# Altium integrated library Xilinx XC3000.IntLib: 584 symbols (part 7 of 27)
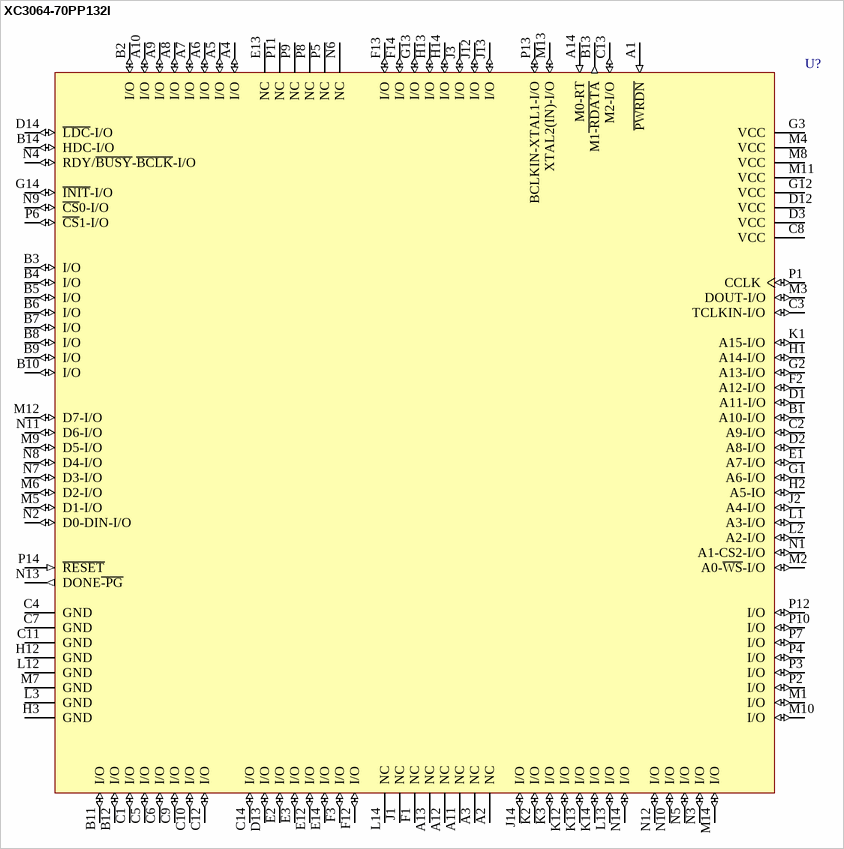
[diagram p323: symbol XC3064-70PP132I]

## XC3064-70PP132I
designator U?
Logic Cell Array with 224 CLBs, with 96 I/O Pins, 132-Pin PGA, Industrial Grade; ComponentAvailability: Not for New Design
footprint PP132 (PGA, 132-Leads, Body 37x37mm, Pitch 2.54mm)
3D model XC3064-PP132 (132-Pin Plastic Pin Grid Array (PP132))
pins: A1 ~{PWRDN} (in), A2 NC, A3 NC, A4 I/O (io), A5 I/O (io), A6 I/O (io), A7 I/O (io), A8 I/O (io), A9 I/O (io), A10 I/O (io), A11 NC, A12 NC, A13 NC, A14 M0-RT (in), B1 A10-I/O (io), B2 I/O (io), B3 I/O (io), B4 I/O (io), B5 I/O (io), B6 I/O (io), B7 I/O (io), B8 I/O (io), B9 I/O (io), B10 I/O (io), B11 I/O (io), B12 I/O (io), B13 M1~{-RDATA} (out), B14 HDC-I/O (io), C1 I/O (io), C2 A9-I/O (io), C3 TCLKIN-I/O (io), C4 GND (power), C5 I/O (io), C6 I/O (io), C7 GND (power), C8 VCC (power), C9 I/O (io), C10 I/O (io), C11 GND (power), C12 I/O (io), C13 M2-I/O (io), C14 I/O (io), D1 A11-I/O (io), D2 A8-I/O (io), D3 VCC (power), D12 VCC (power), D13 I/O (io), D14 ~{LDC}-I/O (io), E1 A7-I/O (io), E2 I/O (io), E3 I/O (io), E12 I/O (io), E13 NC, E14 I/O (io), F1 NC, F2 A12-I/O (io), F3 I/O (io), F12 I/O (io), F13 I/O (io), F14 I/O (io), G1 A6-I/O (io), G2 A13-I/O (io), G3 VCC (power), G12 VCC (power), G13 I/O (io), G14 ~{INIT}-I/O (io), H1 A14-I/O (io), H2 A5-IO (io), H3 GND (power), H12 GND (power), H13 I/O (io), H14 I/O (io), J1 NC, J2 A4-I/O (io), J3 I/O (io), J12 I/O (io), J13 I/O (io), J14 I/O (io), K1 A15-I/O (io), K2 I/O (io), K3 I/O (io), K12 I/O (io), K13 I/O (io), K14 I/O (io), L1 A3-I/O (io), L2 A2-I/O (io), L3 GND (power), L12 GND (power), L13 I/O (io), L14 NC, M1 I/O (io), M2 A0-~{WS}-I/O (io), M3 DOUT-I/O (io), M4 VCC (power), M5 D1-I/O (io), M6 D2-I/O (io), M7 GND (power), M8 VCC (power), M9 D5-I/O (io), M10 I/O (io), M11 VCC (power), M12 D7-I/O (io), M13 XTAL2(IN)-I/O (io), M14 I/O (io), N1 A1-CS2-I/O (io), N2 D0-DIN-I/O (io), N3 I/O (io), N4 RDY/~{BUSY}-~{BCLK}-I/O (io), N5 I/O (io), N6 NC, N7 D3-I/O (io), N8 D4-I/O (io), N9 ~{CS}0-I/O (io), N10 I/O (io), N11 D6-I/O (io), N12 I/O (io), N13 DONE~{-PG} (out), N14 I/O (io), P1 CCLK (io), P2 I/O (io), P3 I/O (io), P4 I/O (io), P5 NC, P6 ~{CS}1-I/O (io), P7 I/O (io), P8 NC, P9 NC, P10 I/O (io), P11 NC, P12 I/O (io), P13 BCLKIN-XTAL1-I/O (io), P14 ~{RESET} (in)

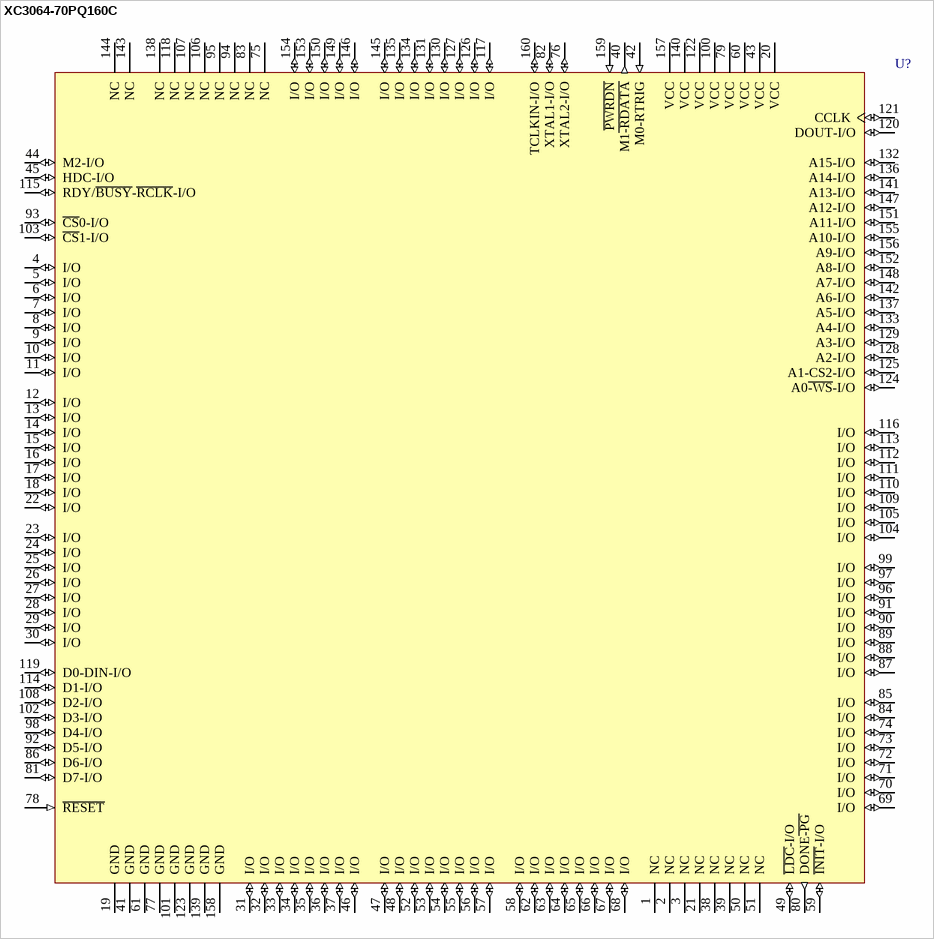
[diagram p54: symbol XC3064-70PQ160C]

## XC3064-70PQ160C
designator U?
Logic Cell Array with 224 CLBs, with 120 I/O Pins, 160-Pin PQFP, Commercial Grade; ComponentAvailability: Not for New Design
footprint PQ160_N (QFP, 160-Leads, Body 28 x 28mm, Pitch 0.65mm, IPC Medium Density)
footprint PQ160_L (QFP, 160-Leads, Body 28 x 28mm, Pitch 0.65mm, IPC High Density)
footprint PQ160_M (QFP, 160-Leads, Body 28 x 28mm, Pitch 0.65mm, IPC Low Density)
3D model XC3064-PQ160 (160-Pin Plastic Quad Flat Pack (PQ160))
pins: 1 NC, 2 NC, 3 NC, 4 I/O (io), 5 I/O (io), 6 I/O (io), 7 I/O (io), 8 I/O (io), 9 I/O (io), 10 I/O (io), 11 I/O (io), 12 I/O (io), 13 I/O (io), 14 I/O (io), 15 I/O (io), 16 I/O (io), 17 I/O (io), 18 I/O (io), 19 GND (power), 20 VCC (power), 21 NC, 22 I/O (io), 23 I/O (io), 24 I/O (io), 25 I/O (io), 26 I/O (io), 27 I/O (io), 28 I/O (io), 29 I/O (io), 30 I/O (io), 31 I/O (io), 32 I/O (io), 33 I/O (io), 34 I/O (io), 35 I/O (io), 36 I/O (io), 37 I/O (io), 38 NC, 39 NC, 40 M1~{-RDATA} (out), 41 GND (power), 42 M0-RTRIG (in), 43 VCC (power), 44 M2-I/O (io), 45 HDC-I/O (io), 46 I/O (io), 47 I/O (io), 48 I/O (io), 49 ~{LDC}-I/O (io), 50 NC, 51 NC, 52 I/O (io), 53 I/O (io), 54 I/O (io), 55 I/O (io), 56 I/O (io), 57 I/O (io), 58 I/O (io), 59 ~{INIT}-I/O (io), 60 VCC (power), 61 GND (power), 62 I/O (io), 63 I/O (io), 64 I/O (io), 65 I/O (io), 66 I/O (io), 67 I/O (io), 68 I/O (io), 69 I/O (io), 70 I/O (io), 71 I/O (io), 72 I/O (io), 73 I/O (io), 74 I/O (io), 75 NC, 76 XTAL2-I/O (io), 77 GND (power), 78 ~{RESET} (in), 79 VCC (power), 80 DONE~{-PG} (out), 81 D7-I/O (io), 82 XTAL1-I/O (io), 83 NC, 84 I/O (io), 85 I/O (io), 86 D6-I/O (io), 87 I/O (io), 88 I/O (io), 89 I/O (io), 90 I/O (io), 91 I/O (io), 92 D5-I/O (io), 93 ~{CS}0-I/O (io), 94 NC, 95 NC, 96 I/O (io), 97 I/O (io), 98 D4-I/O (io), 99 I/O (io), 100 VCC (power), 101 GND (power), 102 D3-I/O (io), 103 ~{CS}1-I/O (io), 104 I/O (io), 105 I/O (io), 106 NC, 107 NC, 108 D2-I/O (io), 109 I/O (io), 110 I/O (io), 111 I/O (io), 112 I/O (io), 113 I/O (io), 114 D1-I/O (io), 115 RDY/~{BUSY}-~{RCLK}-I/O (io), 116 I/O (io), 117 I/O (io), 118 NC, 119 D0-DIN-I/O (io), 120 DOUT-I/O (io), 121 CCLK (io), 122 VCC (power), 123 GND (power), 124 A0~{-WS}-I/O (io), 125 A1-CS2-I/O (io), 126 I/O (io), 127 I/O (io), 128 A2-I/O (io), 129 A3-I/O (io), 130 I/O (io), 131 I/O (io), 132 A15-I/O (io), 133 A4-I/O (io), 134 I/O (io), 135 I/O (io), 136 A14-I/O (io), 137 A5-I/O (io), 138 NC, 139 GND (power), 140 VCC (power), 141 A13-I/O (io), 142 A6-I/O (io), 143 NC, 144 NC, 145 I/O (io), 146 I/O (io), 147 A12-I/O (io), 148 A7-I/O (io), 149 I/O (io), 150 I/O (io), 151 A11-I/O (io), 152 A8-I/O (io), 153 I/O (io), 154 I/O (io), 155 A10-I/O (io), 156 A9-I/O (io), 157 VCC (power), 158 GND (power), 159 ~{PWRDN} (in), 160 TCLKIN-I/O (io)

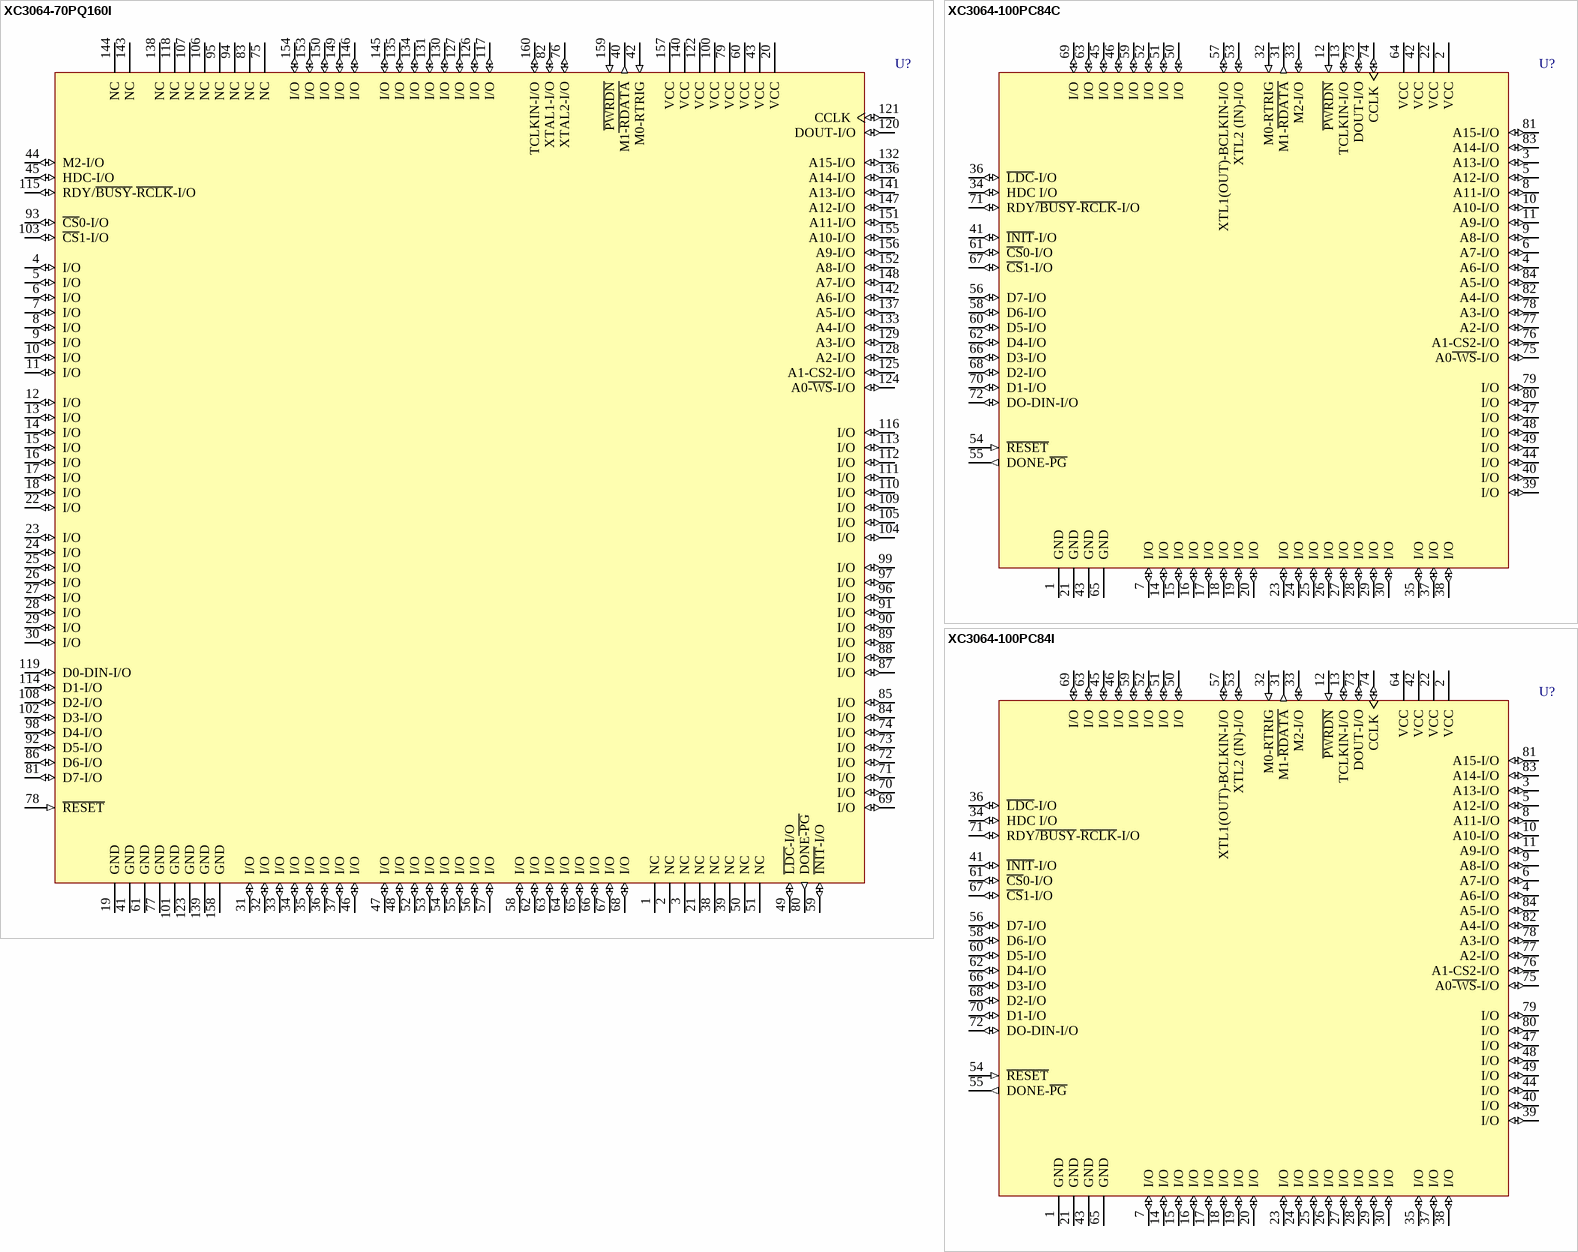
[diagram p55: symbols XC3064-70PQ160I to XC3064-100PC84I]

## XC3064-70PQ160I
designator U?
Logic Cell Array with 224 CLBs, with 120 I/O Pins, 160-Pin PQFP, Industrial Grade; ComponentAvailability: Not for New Design
footprint PQ160_N (QFP, 160-Leads, Body 28 x 28mm, Pitch 0.65mm, IPC Medium Density)
footprint PQ160_L (QFP, 160-Leads, Body 28 x 28mm, Pitch 0.65mm, IPC High Density)
footprint PQ160_M (QFP, 160-Leads, Body 28 x 28mm, Pitch 0.65mm, IPC Low Density)
3D model XC3064-PQ160 (160-Pin Plastic Quad Flat Pack (PQ160))
pins: 1 NC, 2 NC, 3 NC, 4 I/O (io), 5 I/O (io), 6 I/O (io), 7 I/O (io), 8 I/O (io), 9 I/O (io), 10 I/O (io), 11 I/O (io), 12 I/O (io), 13 I/O (io), 14 I/O (io), 15 I/O (io), 16 I/O (io), 17 I/O (io), 18 I/O (io), 19 GND (power), 20 VCC (power), 21 NC, 22 I/O (io), 23 I/O (io), 24 I/O (io), 25 I/O (io), 26 I/O (io), 27 I/O (io), 28 I/O (io), 29 I/O (io), 30 I/O (io), 31 I/O (io), 32 I/O (io), 33 I/O (io), 34 I/O (io), 35 I/O (io), 36 I/O (io), 37 I/O (io), 38 NC, 39 NC, 40 M1~{-RDATA} (out), 41 GND (power), 42 M0-RTRIG (in), 43 VCC (power), 44 M2-I/O (io), 45 HDC-I/O (io), 46 I/O (io), 47 I/O (io), 48 I/O (io), 49 ~{LDC}-I/O (io), 50 NC, 51 NC, 52 I/O (io), 53 I/O (io), 54 I/O (io), 55 I/O (io), 56 I/O (io), 57 I/O (io), 58 I/O (io), 59 ~{INIT}-I/O (io), 60 VCC (power), 61 GND (power), 62 I/O (io), 63 I/O (io), 64 I/O (io), 65 I/O (io), 66 I/O (io), 67 I/O (io), 68 I/O (io), 69 I/O (io), 70 I/O (io), 71 I/O (io), 72 I/O (io), 73 I/O (io), 74 I/O (io), 75 NC, 76 XTAL2-I/O (io), 77 GND (power), 78 ~{RESET} (in), 79 VCC (power), 80 DONE~{-PG} (out), 81 D7-I/O (io), 82 XTAL1-I/O (io), 83 NC, 84 I/O (io), 85 I/O (io), 86 D6-I/O (io), 87 I/O (io), 88 I/O (io), 89 I/O (io), 90 I/O (io), 91 I/O (io), 92 D5-I/O (io), 93 ~{CS}0-I/O (io), 94 NC, 95 NC, 96 I/O (io), 97 I/O (io), 98 D4-I/O (io), 99 I/O (io), 100 VCC (power), 101 GND (power), 102 D3-I/O (io), 103 ~{CS}1-I/O (io), 104 I/O (io), 105 I/O (io), 106 NC, 107 NC, 108 D2-I/O (io), 109 I/O (io), 110 I/O (io), 111 I/O (io), 112 I/O (io), 113 I/O (io), 114 D1-I/O (io), 115 RDY/~{BUSY}-~{RCLK}-I/O (io), 116 I/O (io), 117 I/O (io), 118 NC, 119 D0-DIN-I/O (io), 120 DOUT-I/O (io), 121 CCLK (io), 122 VCC (power), 123 GND (power), 124 A0~{-WS}-I/O (io), 125 A1-CS2-I/O (io), 126 I/O (io), 127 I/O (io), 128 A2-I/O (io), 129 A3-I/O (io), 130 I/O (io), 131 I/O (io), 132 A15-I/O (io), 133 A4-I/O (io), 134 I/O (io), 135 I/O (io), 136 A14-I/O (io), 137 A5-I/O (io), 138 NC, 139 GND (power), 140 VCC (power), 141 A13-I/O (io), 142 A6-I/O (io), 143 NC, 144 NC, 145 I/O (io), 146 I/O (io), 147 A12-I/O (io), 148 A7-I/O (io), 149 I/O (io), 150 I/O (io), 151 A11-I/O (io), 152 A8-I/O (io), 153 I/O (io), 154 I/O (io), 155 A10-I/O (io), 156 A9-I/O (io), 157 VCC (power), 158 GND (power), 159 ~{PWRDN} (in), 160 TCLKIN-I/O (io)

## XC3064-100PC84C
designator U?
Logic Cell Array with 224 CLBs, with 70 I/O Pins, 84-Pin PLCC, Commercial Grade; ComponentAvailability: Not for New Design
footprint PC84_N (Leaded Chip Carrier, 84-Leads, Body 29.3x29.3mm, Pitch 1.27mm, IPC Medium Density)
footprint PC84_L (Leaded Chip Carrier, 84-Leads, Body 29.3x29.3mm, Pitch 1.27mm, IPC High Density)
footprint PC84_M (Leaded Chip Carrier, 84-Leads, Body 29.3x29.3mm, Pitch 1.27mm, IPC Low Density)
3D model XC3064-PC84 (84-Pin Plastic Leaded Chip Carrier (PC84))
pins: 1 GND (power), 2 VCC (power), 3 A13-I/O (io), 4 A6-I/O (io), 5 A12-I/O (io), 6 A7-I/O (io), 7 I/O (io), 8 A11-I/O (io), 9 A8-I/O (io), 10 A10-I/O (io), 11 A9-I/O (io), 12 ~{PWRDN} (in), 13 TCLKIN-I/O (io), 14 I/O (io), 15 I/O (io), 16 I/O (io), 17 I/O (io), 18 I/O (io), 19 I/O (io), 20 I/O (io), 21 GND (power), 22 VCC (power), 23 I/O (io), 24 I/O (io), 25 I/O (io), 26 I/O (io), 27 I/O (io), 28 I/O (io), 29 I/O (io), 30 I/O (io), 31 M1-~{RDATA} (out), 32 M0-RTRIG (in), 33 M2-I/O (io), 34 HDC I/O (io), 35 I/O (io), 36 ~{LDC}-I/O (io), 37 I/O (io), 38 I/O (io), 39 I/O (io), 40 I/O (io), 41 ~{INIT}-I/O (io), 42 VCC (power), 43 GND (power), 44 I/O (io), 45 I/O (io), 46 I/O (io), 47 I/O (io), 48 I/O (io), 49 I/O (io), 50 I/O (io), 51 I/O (io), 52 I/O (io), 53 XTL2 (IN)-I/O (io), 54 ~{RESET} (in), 55 DONE-~{PG} (out), 56 D7-I/O (io), 57 XTL1(OUT)-BCLKIN-I/O (io), 58 D6-I/O (io), 59 I/O (io), 60 D5-I/O (io), 61 ~{CS}0-I/O (io), 62 D4-I/O (io), 63 I/O (io), 64 VCC (power), 65 GND (power), 66 D3-I/O (io), 67 ~{CS}1-I/O (io), 68 D2-I/O (io), 69 I/O (io), 70 D1-I/O (io), 71 RDY~{/BUSY}-~{RCLK}-I/O (io), 72 DO-DIN-I/O (io), 73 DOUT-I/O (io), 74 CCLK (io), 75 A0~{-WS}-I/O (io), 76 A1-CS2-I/O (io), 77 A2-I/O (io), 78 A3-I/O (io), 79 I/O (io), 80 I/O (io), 81 A15-I/O (io), 82 A4-I/O (io), 83 A14-I/O (io), 84 A5-I/O (io)

## XC3064-100PC84I
designator U?
Logic Cell Array with 224 CLBs, with 70 I/O Pins, 84-Pin PLCC, Industrial Grade; ComponentAvailability: Not for New Design
footprint PC84_N (Leaded Chip Carrier, 84-Leads, Body 29.3x29.3mm, Pitch 1.27mm, IPC Medium Density)
footprint PC84_L (Leaded Chip Carrier, 84-Leads, Body 29.3x29.3mm, Pitch 1.27mm, IPC High Density)
footprint PC84_M (Leaded Chip Carrier, 84-Leads, Body 29.3x29.3mm, Pitch 1.27mm, IPC Low Density)
3D model XC3064-PC84 (84-Pin Plastic Leaded Chip Carrier (PC84))
pins: 1 GND (power), 2 VCC (power), 3 A13-I/O (io), 4 A6-I/O (io), 5 A12-I/O (io), 6 A7-I/O (io), 7 I/O (io), 8 A11-I/O (io), 9 A8-I/O (io), 10 A10-I/O (io), 11 A9-I/O (io), 12 ~{PWRDN} (in), 13 TCLKIN-I/O (io), 14 I/O (io), 15 I/O (io), 16 I/O (io), 17 I/O (io), 18 I/O (io), 19 I/O (io), 20 I/O (io), 21 GND (power), 22 VCC (power), 23 I/O (io), 24 I/O (io), 25 I/O (io), 26 I/O (io), 27 I/O (io), 28 I/O (io), 29 I/O (io), 30 I/O (io), 31 M1-~{RDATA} (out), 32 M0-RTRIG (in), 33 M2-I/O (io), 34 HDC I/O (io), 35 I/O (io), 36 ~{LDC}-I/O (io), 37 I/O (io), 38 I/O (io), 39 I/O (io), 40 I/O (io), 41 ~{INIT}-I/O (io), 42 VCC (power), 43 GND (power), 44 I/O (io), 45 I/O (io), 46 I/O (io), 47 I/O (io), 48 I/O (io), 49 I/O (io), 50 I/O (io), 51 I/O (io), 52 I/O (io), 53 XTL2 (IN)-I/O (io), 54 ~{RESET} (in), 55 DONE-~{PG} (out), 56 D7-I/O (io), 57 XTL1(OUT)-BCLKIN-I/O (io), 58 D6-I/O (io), 59 I/O (io), 60 D5-I/O (io), 61 ~{CS}0-I/O (io), 62 D4-I/O (io), 63 I/O (io), 64 VCC (power), 65 GND (power), 66 D3-I/O (io), 67 ~{CS}1-I/O (io), 68 D2-I/O (io), 69 I/O (io), 70 D1-I/O (io), 71 RDY~{/BUSY}-~{RCLK}-I/O (io), 72 DO-DIN-I/O (io), 73 DOUT-I/O (io), 74 CCLK (io), 75 A0~{-WS}-I/O (io), 76 A1-CS2-I/O (io), 77 A2-I/O (io), 78 A3-I/O (io), 79 I/O (io), 80 I/O (io), 81 A15-I/O (io), 82 A4-I/O (io), 83 A14-I/O (io), 84 A5-I/O (io)

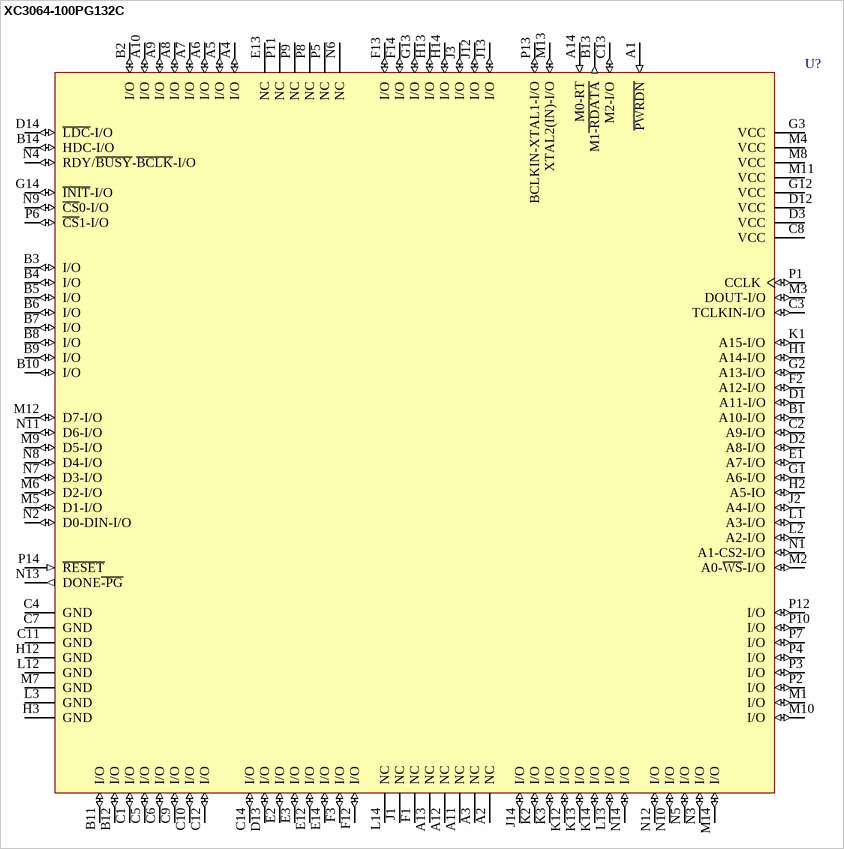
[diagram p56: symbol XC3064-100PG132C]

## XC3064-100PG132C
designator U?
Logic Cell Array with 224 CLBs, with 96 I/O Pins, 132-Pin PGA, Commercial Grade; ComponentAvailability: Not for New Design
footprint PG132 (PGA, 132-Leads, Body 37x37mm, Pitch 2.54mm)
3D model XC3064-PG132 (132-Pin Ceramic Pin Grid Array (PG132))
pins: A1 ~{PWRDN} (in), A2 NC, A3 NC, A4 I/O (io), A5 I/O (io), A6 I/O (io), A7 I/O (io), A8 I/O (io), A9 I/O (io), A10 I/O (io), A11 NC, A12 NC, A13 NC, A14 M0-RT (in), B1 A10-I/O (io), B2 I/O (io), B3 I/O (io), B4 I/O (io), B5 I/O (io), B6 I/O (io), B7 I/O (io), B8 I/O (io), B9 I/O (io), B10 I/O (io), B11 I/O (io), B12 I/O (io), B13 M1~{-RDATA} (out), B14 HDC-I/O (io), C1 I/O (io), C2 A9-I/O (io), C3 TCLKIN-I/O (io), C4 GND (power), C5 I/O (io), C6 I/O (io), C7 GND (power), C8 VCC (power), C9 I/O (io), C10 I/O (io), C11 GND (power), C12 I/O (io), C13 M2-I/O (io), C14 I/O (io), D1 A11-I/O (io), D2 A8-I/O (io), D3 VCC (power), D12 VCC (power), D13 I/O (io), D14 ~{LDC}-I/O (io), E1 A7-I/O (io), E2 I/O (io), E3 I/O (io), E12 I/O (io), E13 NC, E14 I/O (io), F1 NC, F2 A12-I/O (io), F3 I/O (io), F12 I/O (io), F13 I/O (io), F14 I/O (io), G1 A6-I/O (io), G2 A13-I/O (io), G3 VCC (power), G12 VCC (power), G13 I/O (io), G14 ~{INIT}-I/O (io), H1 A14-I/O (io), H2 A5-IO (io), H3 GND (power), H12 GND (power), H13 I/O (io), H14 I/O (io), J1 NC, J2 A4-I/O (io), J3 I/O (io), J12 I/O (io), J13 I/O (io), J14 I/O (io), K1 A15-I/O (io), K2 I/O (io), K3 I/O (io), K12 I/O (io), K13 I/O (io), K14 I/O (io), L1 A3-I/O (io), L2 A2-I/O (io), L3 GND (power), L12 GND (power), L13 I/O (io), L14 NC, M1 I/O (io), M2 A0-~{WS}-I/O (io), M3 DOUT-I/O (io), M4 VCC (power), M5 D1-I/O (io), M6 D2-I/O (io), M7 GND (power), M8 VCC (power), M9 D5-I/O (io), M10 I/O (io), M11 VCC (power), M12 D7-I/O (io), M13 XTAL2(IN)-I/O (io), M14 I/O (io), N1 A1-CS2-I/O (io), N2 D0-DIN-I/O (io), N3 I/O (io), N4 RDY/~{BUSY}-~{BCLK}-I/O (io), N5 I/O (io), N6 NC, N7 D3-I/O (io), N8 D4-I/O (io), N9 ~{CS}0-I/O (io), N10 I/O (io), N11 D6-I/O (io), N12 I/O (io), N13 DONE~{-PG} (out), N14 I/O (io), P1 CCLK (io), P2 I/O (io), P3 I/O (io), P4 I/O (io), P5 NC, P6 ~{CS}1-I/O (io), P7 I/O (io), P8 NC, P9 NC, P10 I/O (io), P11 NC, P12 I/O (io), P13 BCLKIN-XTAL1-I/O (io), P14 ~{RESET} (in)

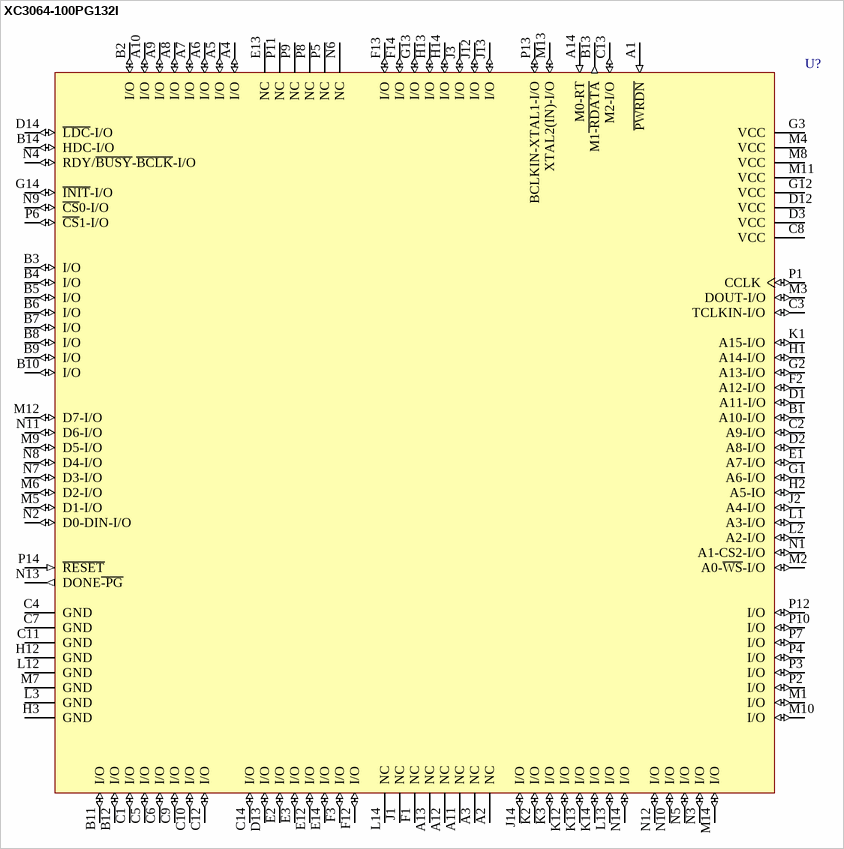
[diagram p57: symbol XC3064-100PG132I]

## XC3064-100PG132I
designator U?
Logic Cell Array with 224 CLBs, with 96 I/O Pins, 132-Pin PGA, Industrial Grade; ComponentAvailability: Not for New Design
footprint PG132 (PGA, 132-Leads, Body 37x37mm, Pitch 2.54mm)
3D model XC3064-PG132 (132-Pin Ceramic Pin Grid Array (PG132))
pins: A1 ~{PWRDN} (in), A2 NC, A3 NC, A4 I/O (io), A5 I/O (io), A6 I/O (io), A7 I/O (io), A8 I/O (io), A9 I/O (io), A10 I/O (io), A11 NC, A12 NC, A13 NC, A14 M0-RT (in), B1 A10-I/O (io), B2 I/O (io), B3 I/O (io), B4 I/O (io), B5 I/O (io), B6 I/O (io), B7 I/O (io), B8 I/O (io), B9 I/O (io), B10 I/O (io), B11 I/O (io), B12 I/O (io), B13 M1~{-RDATA} (out), B14 HDC-I/O (io), C1 I/O (io), C2 A9-I/O (io), C3 TCLKIN-I/O (io), C4 GND (power), C5 I/O (io), C6 I/O (io), C7 GND (power), C8 VCC (power), C9 I/O (io), C10 I/O (io), C11 GND (power), C12 I/O (io), C13 M2-I/O (io), C14 I/O (io), D1 A11-I/O (io), D2 A8-I/O (io), D3 VCC (power), D12 VCC (power), D13 I/O (io), D14 ~{LDC}-I/O (io), E1 A7-I/O (io), E2 I/O (io), E3 I/O (io), E12 I/O (io), E13 NC, E14 I/O (io), F1 NC, F2 A12-I/O (io), F3 I/O (io), F12 I/O (io), F13 I/O (io), F14 I/O (io), G1 A6-I/O (io), G2 A13-I/O (io), G3 VCC (power), G12 VCC (power), G13 I/O (io), G14 ~{INIT}-I/O (io), H1 A14-I/O (io), H2 A5-IO (io), H3 GND (power), H12 GND (power), H13 I/O (io), H14 I/O (io), J1 NC, J2 A4-I/O (io), J3 I/O (io), J12 I/O (io), J13 I/O (io), J14 I/O (io), K1 A15-I/O (io), K2 I/O (io), K3 I/O (io), K12 I/O (io), K13 I/O (io), K14 I/O (io), L1 A3-I/O (io), L2 A2-I/O (io), L3 GND (power), L12 GND (power), L13 I/O (io), L14 NC, M1 I/O (io), M2 A0-~{WS}-I/O (io), M3 DOUT-I/O (io), M4 VCC (power), M5 D1-I/O (io), M6 D2-I/O (io), M7 GND (power), M8 VCC (power), M9 D5-I/O (io), M10 I/O (io), M11 VCC (power), M12 D7-I/O (io), M13 XTAL2(IN)-I/O (io), M14 I/O (io), N1 A1-CS2-I/O (io), N2 D0-DIN-I/O (io), N3 I/O (io), N4 RDY/~{BUSY}-~{BCLK}-I/O (io), N5 I/O (io), N6 NC, N7 D3-I/O (io), N8 D4-I/O (io), N9 ~{CS}0-I/O (io), N10 I/O (io), N11 D6-I/O (io), N12 I/O (io), N13 DONE~{-PG} (out), N14 I/O (io), P1 CCLK (io), P2 I/O (io), P3 I/O (io), P4 I/O (io), P5 NC, P6 ~{CS}1-I/O (io), P7 I/O (io), P8 NC, P9 NC, P10 I/O (io), P11 NC, P12 I/O (io), P13 BCLKIN-XTAL1-I/O (io), P14 ~{RESET} (in)

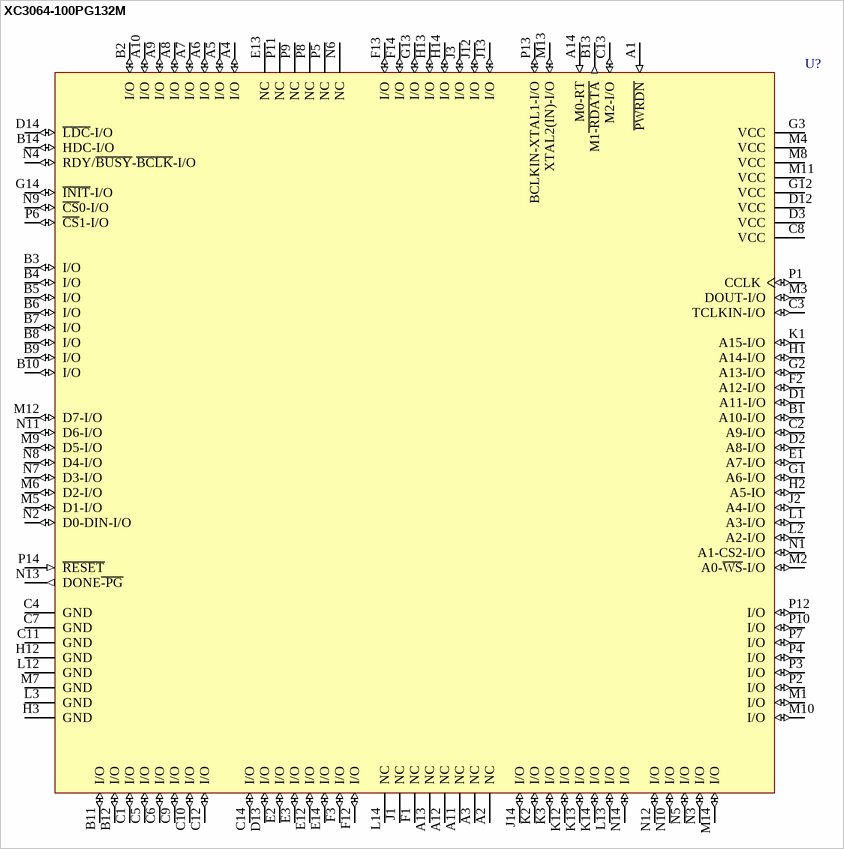
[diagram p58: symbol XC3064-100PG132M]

## XC3064-100PG132M
designator U?
Logic Cell Array with 224 CLBs, with 96 I/O Pins, 132-Pin PGA, Military Grade; ComponentAvailability: Not for New Design
footprint PG132 (PGA, 132-Leads, Body 37x37mm, Pitch 2.54mm)
3D model XC3064-PG132 (132-Pin Ceramic Pin Grid Array (PG132))
pins: A1 ~{PWRDN} (in), A2 NC, A3 NC, A4 I/O (io), A5 I/O (io), A6 I/O (io), A7 I/O (io), A8 I/O (io), A9 I/O (io), A10 I/O (io), A11 NC, A12 NC, A13 NC, A14 M0-RT (in), B1 A10-I/O (io), B2 I/O (io), B3 I/O (io), B4 I/O (io), B5 I/O (io), B6 I/O (io), B7 I/O (io), B8 I/O (io), B9 I/O (io), B10 I/O (io), B11 I/O (io), B12 I/O (io), B13 M1~{-RDATA} (out), B14 HDC-I/O (io), C1 I/O (io), C2 A9-I/O (io), C3 TCLKIN-I/O (io), C4 GND (power), C5 I/O (io), C6 I/O (io), C7 GND (power), C8 VCC (power), C9 I/O (io), C10 I/O (io), C11 GND (power), C12 I/O (io), C13 M2-I/O (io), C14 I/O (io), D1 A11-I/O (io), D2 A8-I/O (io), D3 VCC (power), D12 VCC (power), D13 I/O (io), D14 ~{LDC}-I/O (io), E1 A7-I/O (io), E2 I/O (io), E3 I/O (io), E12 I/O (io), E13 NC, E14 I/O (io), F1 NC, F2 A12-I/O (io), F3 I/O (io), F12 I/O (io), F13 I/O (io), F14 I/O (io), G1 A6-I/O (io), G2 A13-I/O (io), G3 VCC (power), G12 VCC (power), G13 I/O (io), G14 ~{INIT}-I/O (io), H1 A14-I/O (io), H2 A5-IO (io), H3 GND (power), H12 GND (power), H13 I/O (io), H14 I/O (io), J1 NC, J2 A4-I/O (io), J3 I/O (io), J12 I/O (io), J13 I/O (io), J14 I/O (io), K1 A15-I/O (io), K2 I/O (io), K3 I/O (io), K12 I/O (io), K13 I/O (io), K14 I/O (io), L1 A3-I/O (io), L2 A2-I/O (io), L3 GND (power), L12 GND (power), L13 I/O (io), L14 NC, M1 I/O (io), M2 A0-~{WS}-I/O (io), M3 DOUT-I/O (io), M4 VCC (power), M5 D1-I/O (io), M6 D2-I/O (io), M7 GND (power), M8 VCC (power), M9 D5-I/O (io), M10 I/O (io), M11 VCC (power), M12 D7-I/O (io), M13 XTAL2(IN)-I/O (io), M14 I/O (io), N1 A1-CS2-I/O (io), N2 D0-DIN-I/O (io), N3 I/O (io), N4 RDY/~{BUSY}-~{BCLK}-I/O (io), N5 I/O (io), N6 NC, N7 D3-I/O (io), N8 D4-I/O (io), N9 ~{CS}0-I/O (io), N10 I/O (io), N11 D6-I/O (io), N12 I/O (io), N13 DONE~{-PG} (out), N14 I/O (io), P1 CCLK (io), P2 I/O (io), P3 I/O (io), P4 I/O (io), P5 NC, P6 ~{CS}1-I/O (io), P7 I/O (io), P8 NC, P9 NC, P10 I/O (io), P11 NC, P12 I/O (io), P13 BCLKIN-XTAL1-I/O (io), P14 ~{RESET} (in)

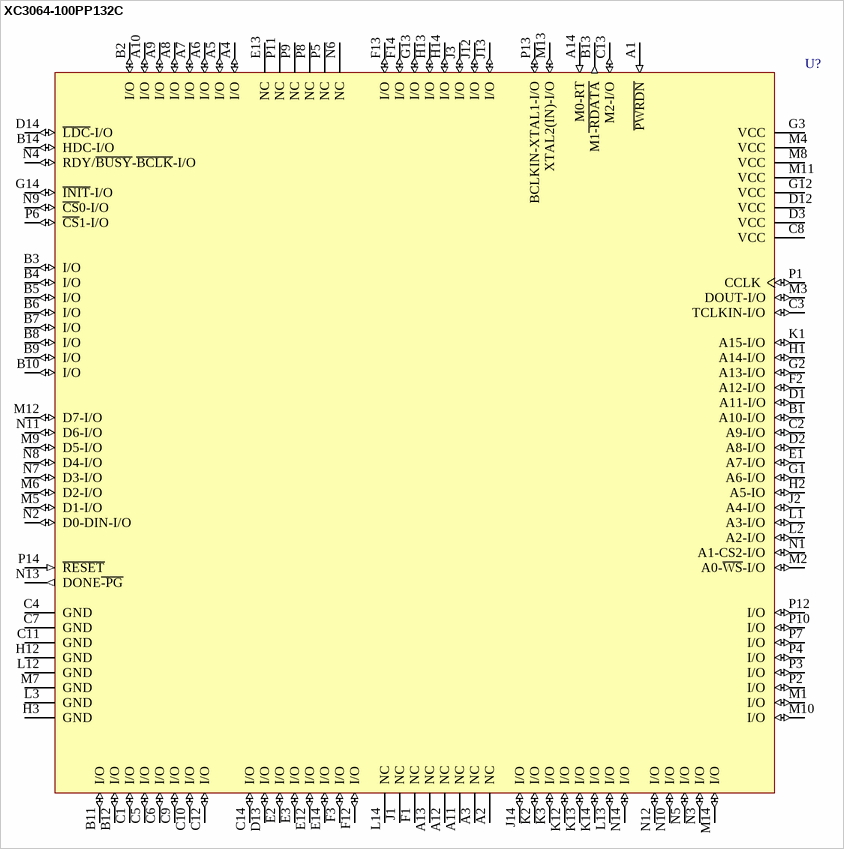
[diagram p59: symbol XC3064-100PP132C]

## XC3064-100PP132C
designator U?
Logic Cell Array with 224 CLBs, with 96 I/O Pins, 132-Pin PGA, Commercial Grade; ComponentAvailability: Not for New Design
footprint PP132 (PGA, 132-Leads, Body 37x37mm, Pitch 2.54mm)
3D model XC3064-PP132 (132-Pin Plastic Pin Grid Array (PP132))
pins: A1 ~{PWRDN} (in), A2 NC, A3 NC, A4 I/O (io), A5 I/O (io), A6 I/O (io), A7 I/O (io), A8 I/O (io), A9 I/O (io), A10 I/O (io), A11 NC, A12 NC, A13 NC, A14 M0-RT (in), B1 A10-I/O (io), B2 I/O (io), B3 I/O (io), B4 I/O (io), B5 I/O (io), B6 I/O (io), B7 I/O (io), B8 I/O (io), B9 I/O (io), B10 I/O (io), B11 I/O (io), B12 I/O (io), B13 M1~{-RDATA} (out), B14 HDC-I/O (io), C1 I/O (io), C2 A9-I/O (io), C3 TCLKIN-I/O (io), C4 GND (power), C5 I/O (io), C6 I/O (io), C7 GND (power), C8 VCC (power), C9 I/O (io), C10 I/O (io), C11 GND (power), C12 I/O (io), C13 M2-I/O (io), C14 I/O (io), D1 A11-I/O (io), D2 A8-I/O (io), D3 VCC (power), D12 VCC (power), D13 I/O (io), D14 ~{LDC}-I/O (io), E1 A7-I/O (io), E2 I/O (io), E3 I/O (io), E12 I/O (io), E13 NC, E14 I/O (io), F1 NC, F2 A12-I/O (io), F3 I/O (io), F12 I/O (io), F13 I/O (io), F14 I/O (io), G1 A6-I/O (io), G2 A13-I/O (io), G3 VCC (power), G12 VCC (power), G13 I/O (io), G14 ~{INIT}-I/O (io), H1 A14-I/O (io), H2 A5-IO (io), H3 GND (power), H12 GND (power), H13 I/O (io), H14 I/O (io), J1 NC, J2 A4-I/O (io), J3 I/O (io), J12 I/O (io), J13 I/O (io), J14 I/O (io), K1 A15-I/O (io), K2 I/O (io), K3 I/O (io), K12 I/O (io), K13 I/O (io), K14 I/O (io), L1 A3-I/O (io), L2 A2-I/O (io), L3 GND (power), L12 GND (power), L13 I/O (io), L14 NC, M1 I/O (io), M2 A0-~{WS}-I/O (io), M3 DOUT-I/O (io), M4 VCC (power), M5 D1-I/O (io), M6 D2-I/O (io), M7 GND (power), M8 VCC (power), M9 D5-I/O (io), M10 I/O (io), M11 VCC (power), M12 D7-I/O (io), M13 XTAL2(IN)-I/O (io), M14 I/O (io), N1 A1-CS2-I/O (io), N2 D0-DIN-I/O (io), N3 I/O (io), N4 RDY/~{BUSY}-~{BCLK}-I/O (io), N5 I/O (io), N6 NC, N7 D3-I/O (io), N8 D4-I/O (io), N9 ~{CS}0-I/O (io), N10 I/O (io), N11 D6-I/O (io), N12 I/O (io), N13 DONE~{-PG} (out), N14 I/O (io), P1 CCLK (io), P2 I/O (io), P3 I/O (io), P4 I/O (io), P5 NC, P6 ~{CS}1-I/O (io), P7 I/O (io), P8 NC, P9 NC, P10 I/O (io), P11 NC, P12 I/O (io), P13 BCLKIN-XTAL1-I/O (io), P14 ~{RESET} (in)

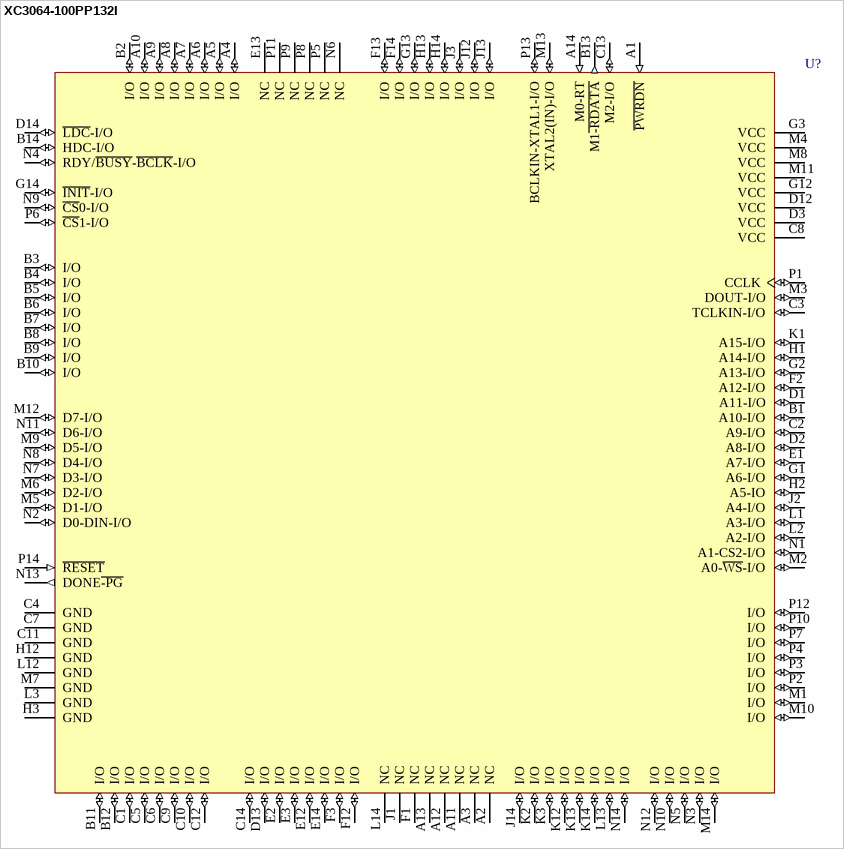
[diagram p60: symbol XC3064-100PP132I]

## XC3064-100PP132I
designator U?
Logic Cell Array with 224 CLBs, with 96 I/O Pins, 132-Pin PGA, Industrial Grade; ComponentAvailability: Not for New Design
footprint PP132 (PGA, 132-Leads, Body 37x37mm, Pitch 2.54mm)
3D model XC3064-PP132 (132-Pin Plastic Pin Grid Array (PP132))
pins: A1 ~{PWRDN} (in), A2 NC, A3 NC, A4 I/O (io), A5 I/O (io), A6 I/O (io), A7 I/O (io), A8 I/O (io), A9 I/O (io), A10 I/O (io), A11 NC, A12 NC, A13 NC, A14 M0-RT (in), B1 A10-I/O (io), B2 I/O (io), B3 I/O (io), B4 I/O (io), B5 I/O (io), B6 I/O (io), B7 I/O (io), B8 I/O (io), B9 I/O (io), B10 I/O (io), B11 I/O (io), B12 I/O (io), B13 M1~{-RDATA} (out), B14 HDC-I/O (io), C1 I/O (io), C2 A9-I/O (io), C3 TCLKIN-I/O (io), C4 GND (power), C5 I/O (io), C6 I/O (io), C7 GND (power), C8 VCC (power), C9 I/O (io), C10 I/O (io), C11 GND (power), C12 I/O (io), C13 M2-I/O (io), C14 I/O (io), D1 A11-I/O (io), D2 A8-I/O (io), D3 VCC (power), D12 VCC (power), D13 I/O (io), D14 ~{LDC}-I/O (io), E1 A7-I/O (io), E2 I/O (io), E3 I/O (io), E12 I/O (io), E13 NC, E14 I/O (io), F1 NC, F2 A12-I/O (io), F3 I/O (io), F12 I/O (io), F13 I/O (io), F14 I/O (io), G1 A6-I/O (io), G2 A13-I/O (io), G3 VCC (power), G12 VCC (power), G13 I/O (io), G14 ~{INIT}-I/O (io), H1 A14-I/O (io), H2 A5-IO (io), H3 GND (power), H12 GND (power), H13 I/O (io), H14 I/O (io), J1 NC, J2 A4-I/O (io), J3 I/O (io), J12 I/O (io), J13 I/O (io), J14 I/O (io), K1 A15-I/O (io), K2 I/O (io), K3 I/O (io), K12 I/O (io), K13 I/O (io), K14 I/O (io), L1 A3-I/O (io), L2 A2-I/O (io), L3 GND (power), L12 GND (power), L13 I/O (io), L14 NC, M1 I/O (io), M2 A0-~{WS}-I/O (io), M3 DOUT-I/O (io), M4 VCC (power), M5 D1-I/O (io), M6 D2-I/O (io), M7 GND (power), M8 VCC (power), M9 D5-I/O (io), M10 I/O (io), M11 VCC (power), M12 D7-I/O (io), M13 XTAL2(IN)-I/O (io), M14 I/O (io), N1 A1-CS2-I/O (io), N2 D0-DIN-I/O (io), N3 I/O (io), N4 RDY/~{BUSY}-~{BCLK}-I/O (io), N5 I/O (io), N6 NC, N7 D3-I/O (io), N8 D4-I/O (io), N9 ~{CS}0-I/O (io), N10 I/O (io), N11 D6-I/O (io), N12 I/O (io), N13 DONE~{-PG} (out), N14 I/O (io), P1 CCLK (io), P2 I/O (io), P3 I/O (io), P4 I/O (io), P5 NC, P6 ~{CS}1-I/O (io), P7 I/O (io), P8 NC, P9 NC, P10 I/O (io), P11 NC, P12 I/O (io), P13 BCLKIN-XTAL1-I/O (io), P14 ~{RESET} (in)

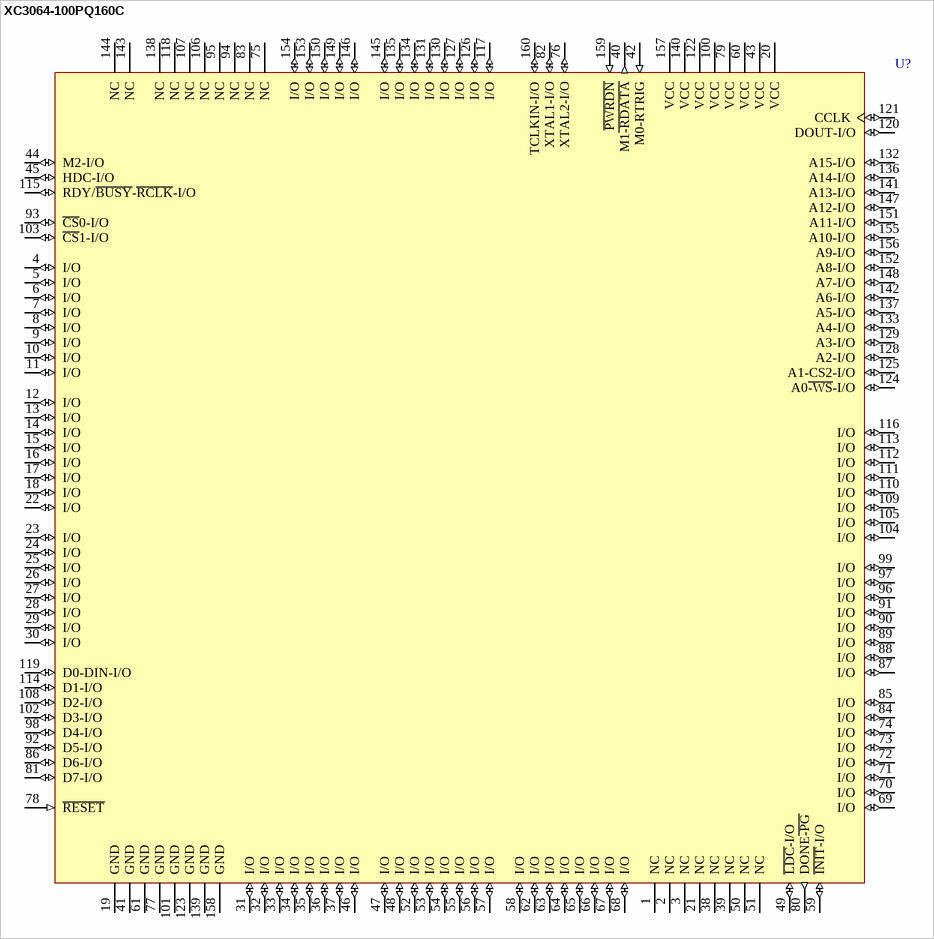
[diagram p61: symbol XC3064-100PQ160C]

## XC3064-100PQ160C
designator U?
Logic Cell Array with 224 CLBs, with 120 I/O Pins, 160-Pin PQFP, Commercial Grade; ComponentAvailability: Not for New Design
footprint PQ160_N (QFP, 160-Leads, Body 28 x 28mm, Pitch 0.65mm, IPC Medium Density)
footprint PQ160_L (QFP, 160-Leads, Body 28 x 28mm, Pitch 0.65mm, IPC High Density)
footprint PQ160_M (QFP, 160-Leads, Body 28 x 28mm, Pitch 0.65mm, IPC Low Density)
3D model XC3064-PQ160 (160-Pin Plastic Quad Flat Pack (PQ160))
pins: 1 NC, 2 NC, 3 NC, 4 I/O (io), 5 I/O (io), 6 I/O (io), 7 I/O (io), 8 I/O (io), 9 I/O (io), 10 I/O (io), 11 I/O (io), 12 I/O (io), 13 I/O (io), 14 I/O (io), 15 I/O (io), 16 I/O (io), 17 I/O (io), 18 I/O (io), 19 GND (power), 20 VCC (power), 21 NC, 22 I/O (io), 23 I/O (io), 24 I/O (io), 25 I/O (io), 26 I/O (io), 27 I/O (io), 28 I/O (io), 29 I/O (io), 30 I/O (io), 31 I/O (io), 32 I/O (io), 33 I/O (io), 34 I/O (io), 35 I/O (io), 36 I/O (io), 37 I/O (io), 38 NC, 39 NC, 40 M1~{-RDATA} (out), 41 GND (power), 42 M0-RTRIG (in), 43 VCC (power), 44 M2-I/O (io), 45 HDC-I/O (io), 46 I/O (io), 47 I/O (io), 48 I/O (io), 49 ~{LDC}-I/O (io), 50 NC, 51 NC, 52 I/O (io), 53 I/O (io), 54 I/O (io), 55 I/O (io), 56 I/O (io), 57 I/O (io), 58 I/O (io), 59 ~{INIT}-I/O (io), 60 VCC (power), 61 GND (power), 62 I/O (io), 63 I/O (io), 64 I/O (io), 65 I/O (io), 66 I/O (io), 67 I/O (io), 68 I/O (io), 69 I/O (io), 70 I/O (io), 71 I/O (io), 72 I/O (io), 73 I/O (io), 74 I/O (io), 75 NC, 76 XTAL2-I/O (io), 77 GND (power), 78 ~{RESET} (in), 79 VCC (power), 80 DONE~{-PG} (out), 81 D7-I/O (io), 82 XTAL1-I/O (io), 83 NC, 84 I/O (io), 85 I/O (io), 86 D6-I/O (io), 87 I/O (io), 88 I/O (io), 89 I/O (io), 90 I/O (io), 91 I/O (io), 92 D5-I/O (io), 93 ~{CS}0-I/O (io), 94 NC, 95 NC, 96 I/O (io), 97 I/O (io), 98 D4-I/O (io), 99 I/O (io), 100 VCC (power), 101 GND (power), 102 D3-I/O (io), 103 ~{CS}1-I/O (io), 104 I/O (io), 105 I/O (io), 106 NC, 107 NC, 108 D2-I/O (io), 109 I/O (io), 110 I/O (io), 111 I/O (io), 112 I/O (io), 113 I/O (io), 114 D1-I/O (io), 115 RDY/~{BUSY}-~{RCLK}-I/O (io), 116 I/O (io), 117 I/O (io), 118 NC, 119 D0-DIN-I/O (io), 120 DOUT-I/O (io), 121 CCLK (io), 122 VCC (power), 123 GND (power), 124 A0~{-WS}-I/O (io), 125 A1-CS2-I/O (io), 126 I/O (io), 127 I/O (io), 128 A2-I/O (io), 129 A3-I/O (io), 130 I/O (io), 131 I/O (io), 132 A15-I/O (io), 133 A4-I/O (io), 134 I/O (io), 135 I/O (io), 136 A14-I/O (io), 137 A5-I/O (io), 138 NC, 139 GND (power), 140 VCC (power), 141 A13-I/O (io), 142 A6-I/O (io), 143 NC, 144 NC, 145 I/O (io), 146 I/O (io), 147 A12-I/O (io), 148 A7-I/O (io), 149 I/O (io), 150 I/O (io), 151 A11-I/O (io), 152 A8-I/O (io), 153 I/O (io), 154 I/O (io), 155 A10-I/O (io), 156 A9-I/O (io), 157 VCC (power), 158 GND (power), 159 ~{PWRDN} (in), 160 TCLKIN-I/O (io)

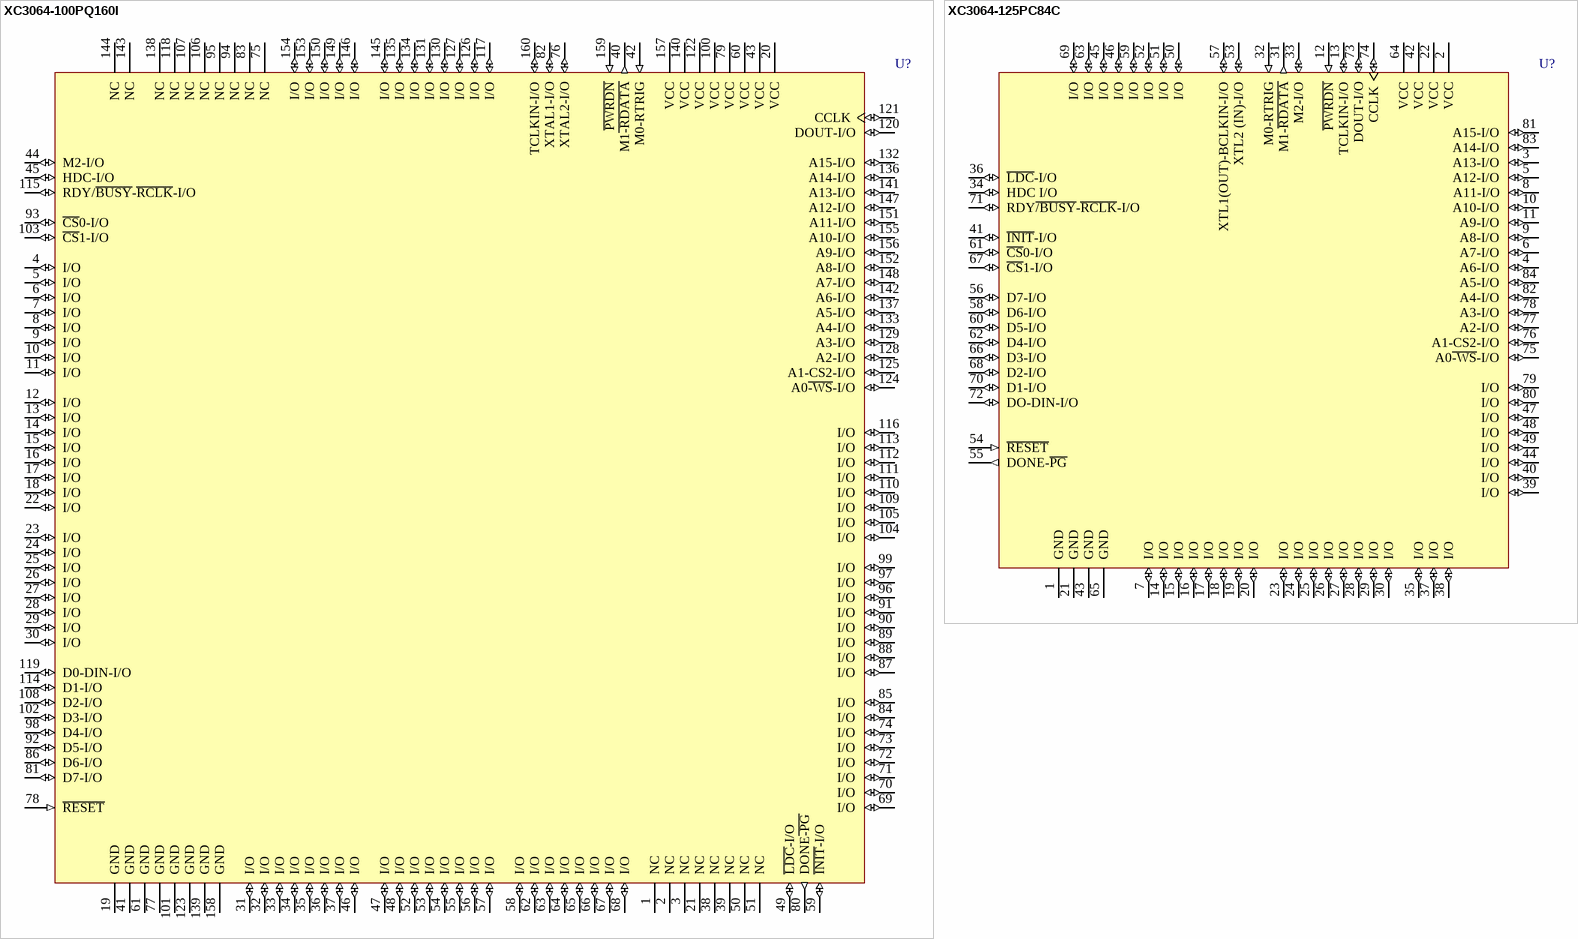
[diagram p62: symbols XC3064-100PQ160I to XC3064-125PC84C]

## XC3064-100PQ160I
designator U?
Logic Cell Array with 224 CLBs, with 120 I/O Pins, 160-Pin PQFP, Industrial Grade; ComponentAvailability: Not for New Design
footprint PQ160_N (QFP, 160-Leads, Body 28 x 28mm, Pitch 0.65mm, IPC Medium Density)
footprint PQ160_L (QFP, 160-Leads, Body 28 x 28mm, Pitch 0.65mm, IPC High Density)
footprint PQ160_M (QFP, 160-Leads, Body 28 x 28mm, Pitch 0.65mm, IPC Low Density)
3D model XC3064-PQ160 (160-Pin Plastic Quad Flat Pack (PQ160))
pins: 1 NC, 2 NC, 3 NC, 4 I/O (io), 5 I/O (io), 6 I/O (io), 7 I/O (io), 8 I/O (io), 9 I/O (io), 10 I/O (io), 11 I/O (io), 12 I/O (io), 13 I/O (io), 14 I/O (io), 15 I/O (io), 16 I/O (io), 17 I/O (io), 18 I/O (io), 19 GND (power), 20 VCC (power), 21 NC, 22 I/O (io), 23 I/O (io), 24 I/O (io), 25 I/O (io), 26 I/O (io), 27 I/O (io), 28 I/O (io), 29 I/O (io), 30 I/O (io), 31 I/O (io), 32 I/O (io), 33 I/O (io), 34 I/O (io), 35 I/O (io), 36 I/O (io), 37 I/O (io), 38 NC, 39 NC, 40 M1~{-RDATA} (out), 41 GND (power), 42 M0-RTRIG (in), 43 VCC (power), 44 M2-I/O (io), 45 HDC-I/O (io), 46 I/O (io), 47 I/O (io), 48 I/O (io), 49 ~{LDC}-I/O (io), 50 NC, 51 NC, 52 I/O (io), 53 I/O (io), 54 I/O (io), 55 I/O (io), 56 I/O (io), 57 I/O (io), 58 I/O (io), 59 ~{INIT}-I/O (io), 60 VCC (power), 61 GND (power), 62 I/O (io), 63 I/O (io), 64 I/O (io), 65 I/O (io), 66 I/O (io), 67 I/O (io), 68 I/O (io), 69 I/O (io), 70 I/O (io), 71 I/O (io), 72 I/O (io), 73 I/O (io), 74 I/O (io), 75 NC, 76 XTAL2-I/O (io), 77 GND (power), 78 ~{RESET} (in), 79 VCC (power), 80 DONE~{-PG} (out), 81 D7-I/O (io), 82 XTAL1-I/O (io), 83 NC, 84 I/O (io), 85 I/O (io), 86 D6-I/O (io), 87 I/O (io), 88 I/O (io), 89 I/O (io), 90 I/O (io), 91 I/O (io), 92 D5-I/O (io), 93 ~{CS}0-I/O (io), 94 NC, 95 NC, 96 I/O (io), 97 I/O (io), 98 D4-I/O (io), 99 I/O (io), 100 VCC (power), 101 GND (power), 102 D3-I/O (io), 103 ~{CS}1-I/O (io), 104 I/O (io), 105 I/O (io), 106 NC, 107 NC, 108 D2-I/O (io), 109 I/O (io), 110 I/O (io), 111 I/O (io), 112 I/O (io), 113 I/O (io), 114 D1-I/O (io), 115 RDY/~{BUSY}-~{RCLK}-I/O (io), 116 I/O (io), 117 I/O (io), 118 NC, 119 D0-DIN-I/O (io), 120 DOUT-I/O (io), 121 CCLK (io), 122 VCC (power), 123 GND (power), 124 A0~{-WS}-I/O (io), 125 A1-CS2-I/O (io), 126 I/O (io), 127 I/O (io), 128 A2-I/O (io), 129 A3-I/O (io), 130 I/O (io), 131 I/O (io), 132 A15-I/O (io), 133 A4-I/O (io), 134 I/O (io), 135 I/O (io), 136 A14-I/O (io), 137 A5-I/O (io), 138 NC, 139 GND (power), 140 VCC (power), 141 A13-I/O (io), 142 A6-I/O (io), 143 NC, 144 NC, 145 I/O (io), 146 I/O (io), 147 A12-I/O (io), 148 A7-I/O (io), 149 I/O (io), 150 I/O (io), 151 A11-I/O (io), 152 A8-I/O (io), 153 I/O (io), 154 I/O (io), 155 A10-I/O (io), 156 A9-I/O (io), 157 VCC (power), 158 GND (power), 159 ~{PWRDN} (in), 160 TCLKIN-I/O (io)

## XC3064-125PC84C
designator U?
Logic Cell Array with 224 CLBs, with 70 I/O Pins, 84-Pin PLCC, Commercial Grade; ComponentAvailability: Not for New Design
footprint PC84_N (Leaded Chip Carrier, 84-Leads, Body 29.3x29.3mm, Pitch 1.27mm, IPC Medium Density)
footprint PC84_L (Leaded Chip Carrier, 84-Leads, Body 29.3x29.3mm, Pitch 1.27mm, IPC High Density)
footprint PC84_M (Leaded Chip Carrier, 84-Leads, Body 29.3x29.3mm, Pitch 1.27mm, IPC Low Density)
3D model XC3064-PC84 (84-Pin Plastic Leaded Chip Carrier (PC84))
pins: 1 GND (power), 2 VCC (power), 3 A13-I/O (io), 4 A6-I/O (io), 5 A12-I/O (io), 6 A7-I/O (io), 7 I/O (io), 8 A11-I/O (io), 9 A8-I/O (io), 10 A10-I/O (io), 11 A9-I/O (io), 12 ~{PWRDN} (in), 13 TCLKIN-I/O (io), 14 I/O (io), 15 I/O (io), 16 I/O (io), 17 I/O (io), 18 I/O (io), 19 I/O (io), 20 I/O (io), 21 GND (power), 22 VCC (power), 23 I/O (io), 24 I/O (io), 25 I/O (io), 26 I/O (io), 27 I/O (io), 28 I/O (io), 29 I/O (io), 30 I/O (io), 31 M1-~{RDATA} (out), 32 M0-RTRIG (in), 33 M2-I/O (io), 34 HDC I/O (io), 35 I/O (io), 36 ~{LDC}-I/O (io), 37 I/O (io), 38 I/O (io), 39 I/O (io), 40 I/O (io), 41 ~{INIT}-I/O (io), 42 VCC (power), 43 GND (power), 44 I/O (io), 45 I/O (io), 46 I/O (io), 47 I/O (io), 48 I/O (io), 49 I/O (io), 50 I/O (io), 51 I/O (io), 52 I/O (io), 53 XTL2 (IN)-I/O (io), 54 ~{RESET} (in), 55 DONE-~{PG} (out), 56 D7-I/O (io), 57 XTL1(OUT)-BCLKIN-I/O (io), 58 D6-I/O (io), 59 I/O (io), 60 D5-I/O (io), 61 ~{CS}0-I/O (io), 62 D4-I/O (io), 63 I/O (io), 64 VCC (power), 65 GND (power), 66 D3-I/O (io), 67 ~{CS}1-I/O (io), 68 D2-I/O (io), 69 I/O (io), 70 D1-I/O (io), 71 RDY~{/BUSY}-~{RCLK}-I/O (io), 72 DO-DIN-I/O (io), 73 DOUT-I/O (io), 74 CCLK (io), 75 A0~{-WS}-I/O (io), 76 A1-CS2-I/O (io), 77 A2-I/O (io), 78 A3-I/O (io), 79 I/O (io), 80 I/O (io), 81 A15-I/O (io), 82 A4-I/O (io), 83 A14-I/O (io), 84 A5-I/O (io)

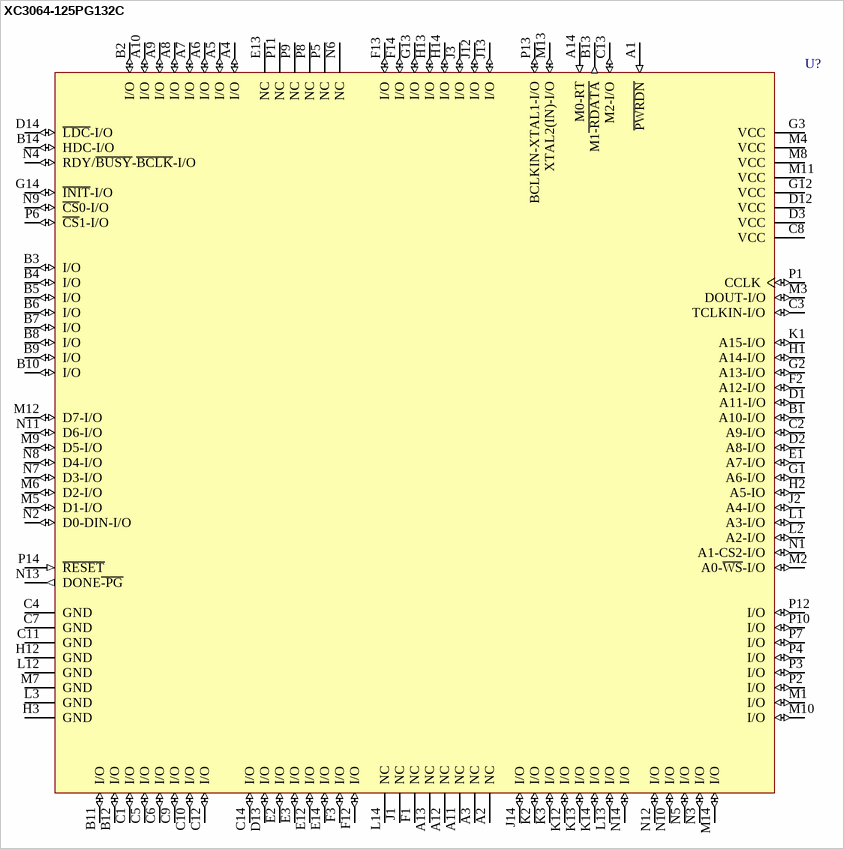
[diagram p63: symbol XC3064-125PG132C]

## XC3064-125PG132C
designator U?
Logic Cell Array with 224 CLBs, with 96 I/O Pins, 132-Pin PGA, Commercial Grade; ComponentAvailability: Not for New Design
footprint PG132 (PGA, 132-Leads, Body 37x37mm, Pitch 2.54mm)
3D model XC3064-PG132 (132-Pin Ceramic Pin Grid Array (PG132))
pins: A1 ~{PWRDN} (in), A2 NC, A3 NC, A4 I/O (io), A5 I/O (io), A6 I/O (io), A7 I/O (io), A8 I/O (io), A9 I/O (io), A10 I/O (io), A11 NC, A12 NC, A13 NC, A14 M0-RT (in), B1 A10-I/O (io), B2 I/O (io), B3 I/O (io), B4 I/O (io), B5 I/O (io), B6 I/O (io), B7 I/O (io), B8 I/O (io), B9 I/O (io), B10 I/O (io), B11 I/O (io), B12 I/O (io), B13 M1~{-RDATA} (out), B14 HDC-I/O (io), C1 I/O (io), C2 A9-I/O (io), C3 TCLKIN-I/O (io), C4 GND (power), C5 I/O (io), C6 I/O (io), C7 GND (power), C8 VCC (power), C9 I/O (io), C10 I/O (io), C11 GND (power), C12 I/O (io), C13 M2-I/O (io), C14 I/O (io), D1 A11-I/O (io), D2 A8-I/O (io), D3 VCC (power), D12 VCC (power), D13 I/O (io), D14 ~{LDC}-I/O (io), E1 A7-I/O (io), E2 I/O (io), E3 I/O (io), E12 I/O (io), E13 NC, E14 I/O (io), F1 NC, F2 A12-I/O (io), F3 I/O (io), F12 I/O (io), F13 I/O (io), F14 I/O (io), G1 A6-I/O (io), G2 A13-I/O (io), G3 VCC (power), G12 VCC (power), G13 I/O (io), G14 ~{INIT}-I/O (io), H1 A14-I/O (io), H2 A5-IO (io), H3 GND (power), H12 GND (power), H13 I/O (io), H14 I/O (io), J1 NC, J2 A4-I/O (io), J3 I/O (io), J12 I/O (io), J13 I/O (io), J14 I/O (io), K1 A15-I/O (io), K2 I/O (io), K3 I/O (io), K12 I/O (io), K13 I/O (io), K14 I/O (io), L1 A3-I/O (io), L2 A2-I/O (io), L3 GND (power), L12 GND (power), L13 I/O (io), L14 NC, M1 I/O (io), M2 A0-~{WS}-I/O (io), M3 DOUT-I/O (io), M4 VCC (power), M5 D1-I/O (io), M6 D2-I/O (io), M7 GND (power), M8 VCC (power), M9 D5-I/O (io), M10 I/O (io), M11 VCC (power), M12 D7-I/O (io), M13 XTAL2(IN)-I/O (io), M14 I/O (io), N1 A1-CS2-I/O (io), N2 D0-DIN-I/O (io), N3 I/O (io), N4 RDY/~{BUSY}-~{BCLK}-I/O (io), N5 I/O (io), N6 NC, N7 D3-I/O (io), N8 D4-I/O (io), N9 ~{CS}0-I/O (io), N10 I/O (io), N11 D6-I/O (io), N12 I/O (io), N13 DONE~{-PG} (out), N14 I/O (io), P1 CCLK (io), P2 I/O (io), P3 I/O (io), P4 I/O (io), P5 NC, P6 ~{CS}1-I/O (io), P7 I/O (io), P8 NC, P9 NC, P10 I/O (io), P11 NC, P12 I/O (io), P13 BCLKIN-XTAL1-I/O (io), P14 ~{RESET} (in)

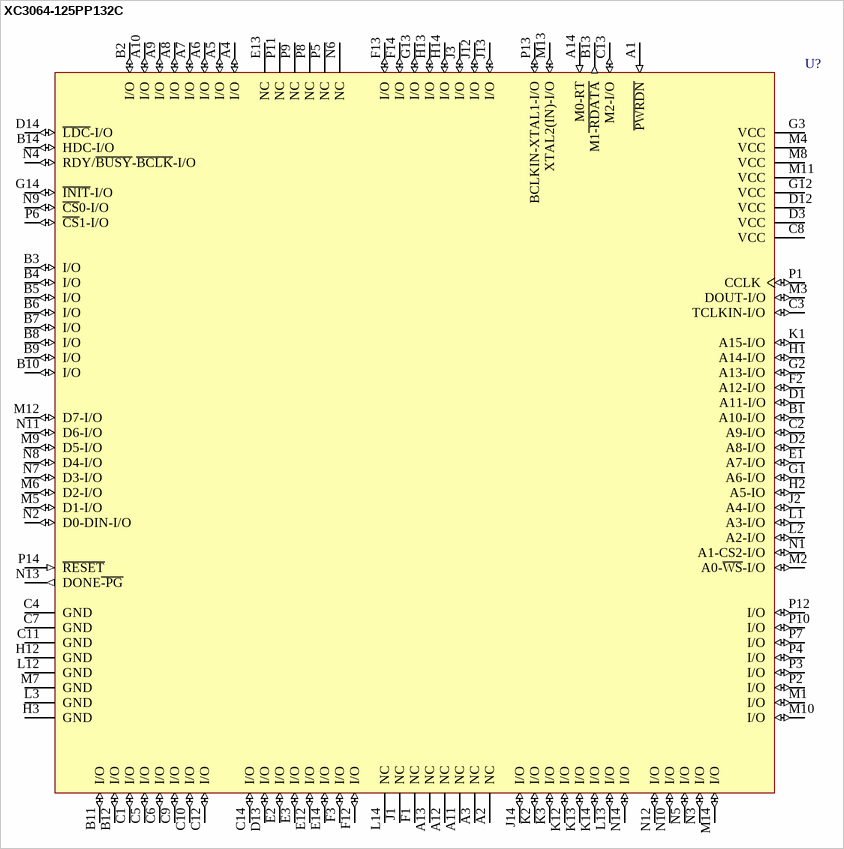
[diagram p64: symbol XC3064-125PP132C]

## XC3064-125PP132C
designator U?
Logic Cell Array with 224 CLBs, with 96 I/O Pins, 132-Pin PGA, Commercial Grade; ComponentAvailability: Not for New Design
footprint PP132 (PGA, 132-Leads, Body 37x37mm, Pitch 2.54mm)
3D model XC3064-PP132 (132-Pin Plastic Pin Grid Array (PP132))
pins: A1 ~{PWRDN} (in), A2 NC, A3 NC, A4 I/O (io), A5 I/O (io), A6 I/O (io), A7 I/O (io), A8 I/O (io), A9 I/O (io), A10 I/O (io), A11 NC, A12 NC, A13 NC, A14 M0-RT (in), B1 A10-I/O (io), B2 I/O (io), B3 I/O (io), B4 I/O (io), B5 I/O (io), B6 I/O (io), B7 I/O (io), B8 I/O (io), B9 I/O (io), B10 I/O (io), B11 I/O (io), B12 I/O (io), B13 M1~{-RDATA} (out), B14 HDC-I/O (io), C1 I/O (io), C2 A9-I/O (io), C3 TCLKIN-I/O (io), C4 GND (power), C5 I/O (io), C6 I/O (io), C7 GND (power), C8 VCC (power), C9 I/O (io), C10 I/O (io), C11 GND (power), C12 I/O (io), C13 M2-I/O (io), C14 I/O (io), D1 A11-I/O (io), D2 A8-I/O (io), D3 VCC (power), D12 VCC (power), D13 I/O (io), D14 ~{LDC}-I/O (io), E1 A7-I/O (io), E2 I/O (io), E3 I/O (io), E12 I/O (io), E13 NC, E14 I/O (io), F1 NC, F2 A12-I/O (io), F3 I/O (io), F12 I/O (io), F13 I/O (io), F14 I/O (io), G1 A6-I/O (io), G2 A13-I/O (io), G3 VCC (power), G12 VCC (power), G13 I/O (io), G14 ~{INIT}-I/O (io), H1 A14-I/O (io), H2 A5-IO (io), H3 GND (power), H12 GND (power), H13 I/O (io), H14 I/O (io), J1 NC, J2 A4-I/O (io), J3 I/O (io), J12 I/O (io), J13 I/O (io), J14 I/O (io), K1 A15-I/O (io), K2 I/O (io), K3 I/O (io), K12 I/O (io), K13 I/O (io), K14 I/O (io), L1 A3-I/O (io), L2 A2-I/O (io), L3 GND (power), L12 GND (power), L13 I/O (io), L14 NC, M1 I/O (io), M2 A0-~{WS}-I/O (io), M3 DOUT-I/O (io), M4 VCC (power), M5 D1-I/O (io), M6 D2-I/O (io), M7 GND (power), M8 VCC (power), M9 D5-I/O (io), M10 I/O (io), M11 VCC (power), M12 D7-I/O (io), M13 XTAL2(IN)-I/O (io), M14 I/O (io), N1 A1-CS2-I/O (io), N2 D0-DIN-I/O (io), N3 I/O (io), N4 RDY/~{BUSY}-~{BCLK}-I/O (io), N5 I/O (io), N6 NC, N7 D3-I/O (io), N8 D4-I/O (io), N9 ~{CS}0-I/O (io), N10 I/O (io), N11 D6-I/O (io), N12 I/O (io), N13 DONE~{-PG} (out), N14 I/O (io), P1 CCLK (io), P2 I/O (io), P3 I/O (io), P4 I/O (io), P5 NC, P6 ~{CS}1-I/O (io), P7 I/O (io), P8 NC, P9 NC, P10 I/O (io), P11 NC, P12 I/O (io), P13 BCLKIN-XTAL1-I/O (io), P14 ~{RESET} (in)

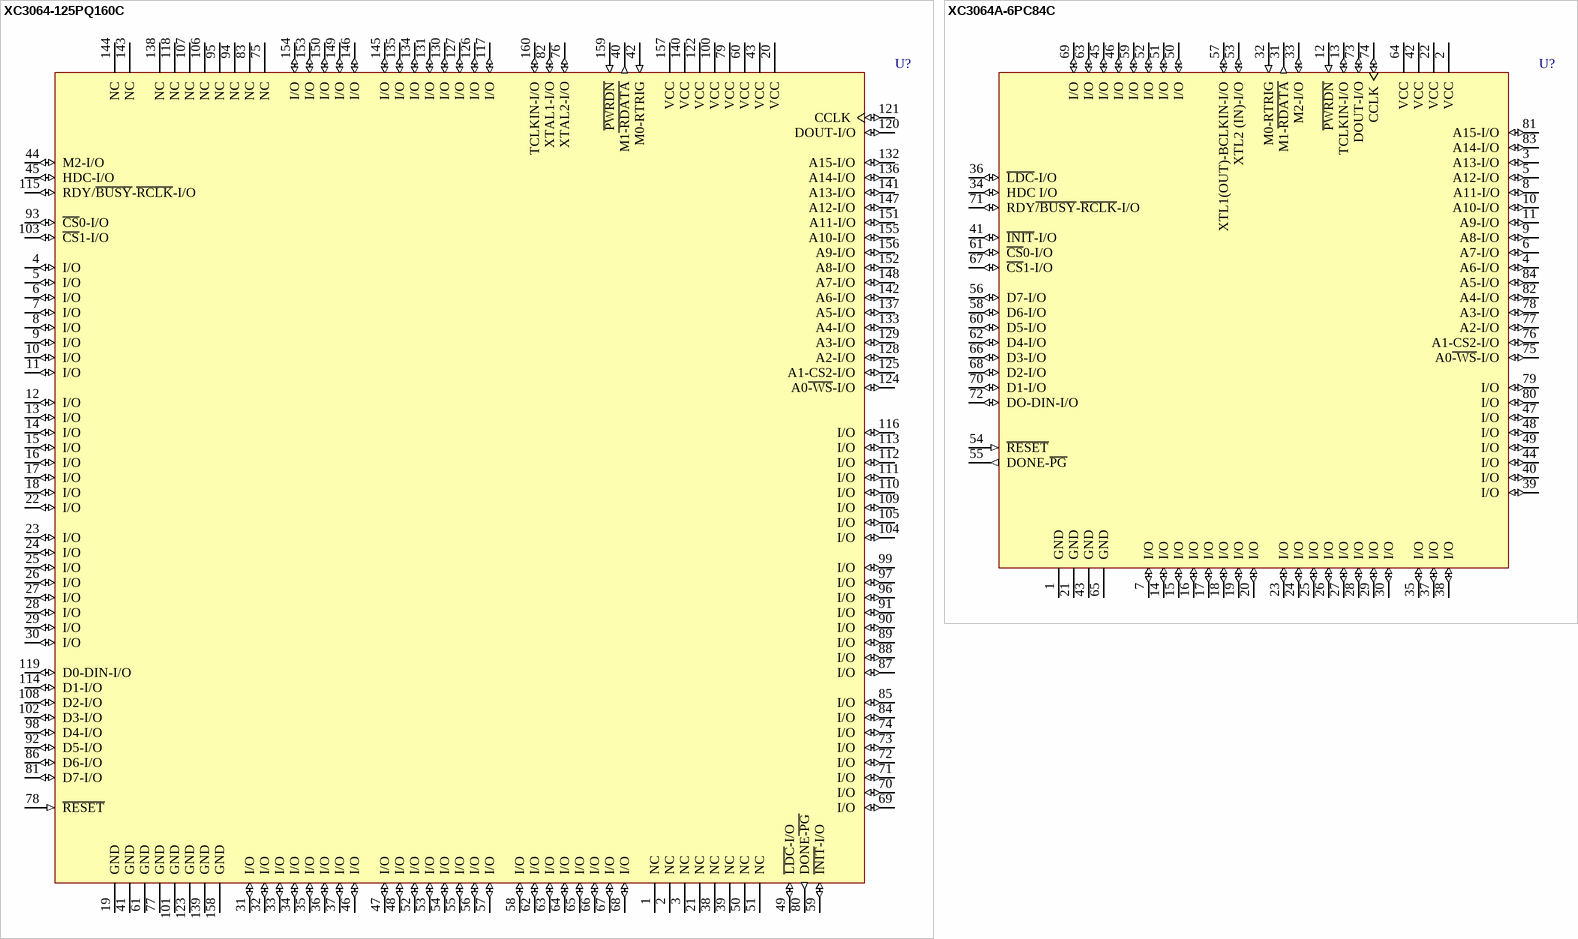
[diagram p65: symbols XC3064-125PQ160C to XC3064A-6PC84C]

## XC3064-125PQ160C
designator U?
Logic Cell Array with 224 CLBs, with 120 I/O Pins, 160-Pin PQFP, Commercial Grade; ComponentAvailability: Not for New Design
footprint PQ160_N (QFP, 160-Leads, Body 28 x 28mm, Pitch 0.65mm, IPC Medium Density)
footprint PQ160_L (QFP, 160-Leads, Body 28 x 28mm, Pitch 0.65mm, IPC High Density)
footprint PQ160_M (QFP, 160-Leads, Body 28 x 28mm, Pitch 0.65mm, IPC Low Density)
3D model XC3064-PQ160 (160-Pin Plastic Quad Flat Pack (PQ160))
pins: 1 NC, 2 NC, 3 NC, 4 I/O (io), 5 I/O (io), 6 I/O (io), 7 I/O (io), 8 I/O (io), 9 I/O (io), 10 I/O (io), 11 I/O (io), 12 I/O (io), 13 I/O (io), 14 I/O (io), 15 I/O (io), 16 I/O (io), 17 I/O (io), 18 I/O (io), 19 GND (power), 20 VCC (power), 21 NC, 22 I/O (io), 23 I/O (io), 24 I/O (io), 25 I/O (io), 26 I/O (io), 27 I/O (io), 28 I/O (io), 29 I/O (io), 30 I/O (io), 31 I/O (io), 32 I/O (io), 33 I/O (io), 34 I/O (io), 35 I/O (io), 36 I/O (io), 37 I/O (io), 38 NC, 39 NC, 40 M1~{-RDATA} (out), 41 GND (power), 42 M0-RTRIG (in), 43 VCC (power), 44 M2-I/O (io), 45 HDC-I/O (io), 46 I/O (io), 47 I/O (io), 48 I/O (io), 49 ~{LDC}-I/O (io), 50 NC, 51 NC, 52 I/O (io), 53 I/O (io), 54 I/O (io), 55 I/O (io), 56 I/O (io), 57 I/O (io), 58 I/O (io), 59 ~{INIT}-I/O (io), 60 VCC (power), 61 GND (power), 62 I/O (io), 63 I/O (io), 64 I/O (io), 65 I/O (io), 66 I/O (io), 67 I/O (io), 68 I/O (io), 69 I/O (io), 70 I/O (io), 71 I/O (io), 72 I/O (io), 73 I/O (io), 74 I/O (io), 75 NC, 76 XTAL2-I/O (io), 77 GND (power), 78 ~{RESET} (in), 79 VCC (power), 80 DONE~{-PG} (out), 81 D7-I/O (io), 82 XTAL1-I/O (io), 83 NC, 84 I/O (io), 85 I/O (io), 86 D6-I/O (io), 87 I/O (io), 88 I/O (io), 89 I/O (io), 90 I/O (io), 91 I/O (io), 92 D5-I/O (io), 93 ~{CS}0-I/O (io), 94 NC, 95 NC, 96 I/O (io), 97 I/O (io), 98 D4-I/O (io), 99 I/O (io), 100 VCC (power), 101 GND (power), 102 D3-I/O (io), 103 ~{CS}1-I/O (io), 104 I/O (io), 105 I/O (io), 106 NC, 107 NC, 108 D2-I/O (io), 109 I/O (io), 110 I/O (io), 111 I/O (io), 112 I/O (io), 113 I/O (io), 114 D1-I/O (io), 115 RDY/~{BUSY}-~{RCLK}-I/O (io), 116 I/O (io), 117 I/O (io), 118 NC, 119 D0-DIN-I/O (io), 120 DOUT-I/O (io), 121 CCLK (io), 122 VCC (power), 123 GND (power), 124 A0~{-WS}-I/O (io), 125 A1-CS2-I/O (io), 126 I/O (io), 127 I/O (io), 128 A2-I/O (io), 129 A3-I/O (io), 130 I/O (io), 131 I/O (io), 132 A15-I/O (io), 133 A4-I/O (io), 134 I/O (io), 135 I/O (io), 136 A14-I/O (io), 137 A5-I/O (io), 138 NC, 139 GND (power), 140 VCC (power), 141 A13-I/O (io), 142 A6-I/O (io), 143 NC, 144 NC, 145 I/O (io), 146 I/O (io), 147 A12-I/O (io), 148 A7-I/O (io), 149 I/O (io), 150 I/O (io), 151 A11-I/O (io), 152 A8-I/O (io), 153 I/O (io), 154 I/O (io), 155 A10-I/O (io), 156 A9-I/O (io), 157 VCC (power), 158 GND (power), 159 ~{PWRDN} (in), 160 TCLKIN-I/O (io)

## XC3064A-6PC84C
designator U?
Logic Cell Array with 224 CLBs, with 70 I/O Pins, 84-Pin PLCC, Commercial Grade; ComponentAvailability: Not for New Design
footprint PC84_N (Leaded Chip Carrier, 84-Leads, Body 29.3x29.3mm, Pitch 1.27mm, IPC Medium Density)
footprint PC84_L (Leaded Chip Carrier, 84-Leads, Body 29.3x29.3mm, Pitch 1.27mm, IPC High Density)
footprint PC84_M (Leaded Chip Carrier, 84-Leads, Body 29.3x29.3mm, Pitch 1.27mm, IPC Low Density)
3D model XC3064A-PC84 (84-Pin Plastic Leaded Chip Carrier (PC84))
pins: 1 GND (power), 2 VCC (power), 3 A13-I/O (io), 4 A6-I/O (io), 5 A12-I/O (io), 6 A7-I/O (io), 7 I/O (io), 8 A11-I/O (io), 9 A8-I/O (io), 10 A10-I/O (io), 11 A9-I/O (io), 12 ~{PWRDN} (in), 13 TCLKIN-I/O (io), 14 I/O (io), 15 I/O (io), 16 I/O (io), 17 I/O (io), 18 I/O (io), 19 I/O (io), 20 I/O (io), 21 GND (power), 22 VCC (power), 23 I/O (io), 24 I/O (io), 25 I/O (io), 26 I/O (io), 27 I/O (io), 28 I/O (io), 29 I/O (io), 30 I/O (io), 31 M1-~{RDATA} (out), 32 M0-RTRIG (in), 33 M2-I/O (io), 34 HDC I/O (io), 35 I/O (io), 36 ~{LDC}-I/O (io), 37 I/O (io), 38 I/O (io), 39 I/O (io), 40 I/O (io), 41 ~{INIT}-I/O (io), 42 VCC (power), 43 GND (power), 44 I/O (io), 45 I/O (io), 46 I/O (io), 47 I/O (io), 48 I/O (io), 49 I/O (io), 50 I/O (io), 51 I/O (io), 52 I/O (io), 53 XTL2 (IN)-I/O (io), 54 ~{RESET} (in), 55 DONE-~{PG} (out), 56 D7-I/O (io), 57 XTL1(OUT)-BCLKIN-I/O (io), 58 D6-I/O (io), 59 I/O (io), 60 D5-I/O (io), 61 ~{CS}0-I/O (io), 62 D4-I/O (io), 63 I/O (io), 64 VCC (power), 65 GND (power), 66 D3-I/O (io), 67 ~{CS}1-I/O (io), 68 D2-I/O (io), 69 I/O (io), 70 D1-I/O (io), 71 RDY~{/BUSY}-~{RCLK}-I/O (io), 72 DO-DIN-I/O (io), 73 DOUT-I/O (io), 74 CCLK (io), 75 A0~{-WS}-I/O (io), 76 A1-CS2-I/O (io), 77 A2-I/O (io), 78 A3-I/O (io), 79 I/O (io), 80 I/O (io), 81 A15-I/O (io), 82 A4-I/O (io), 83 A14-I/O (io), 84 A5-I/O (io)

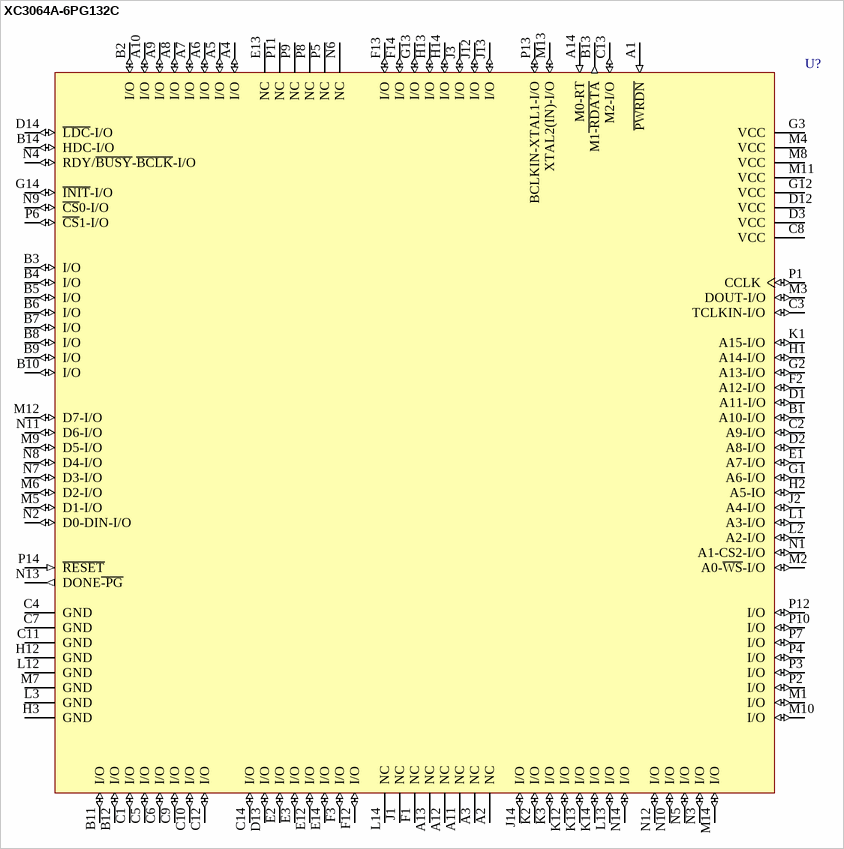
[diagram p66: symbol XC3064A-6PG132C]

## XC3064A-6PG132C
designator U?
Logic Cell Array with 224 CLBs, with 96 I/O Pins, 132-Pin PGA, Commercial Grade; ComponentAvailability: Not for New Design
footprint PG132 (PGA, 132-Leads, Body 37x37mm, Pitch 2.54mm)
3D model XC3064A-PG132 (132-Pin Ceramic Pin Grid Array (PG132))
pins: A1 ~{PWRDN} (in), A2 NC, A3 NC, A4 I/O (io), A5 I/O (io), A6 I/O (io), A7 I/O (io), A8 I/O (io), A9 I/O (io), A10 I/O (io), A11 NC, A12 NC, A13 NC, A14 M0-RT (in), B1 A10-I/O (io), B2 I/O (io), B3 I/O (io), B4 I/O (io), B5 I/O (io), B6 I/O (io), B7 I/O (io), B8 I/O (io), B9 I/O (io), B10 I/O (io), B11 I/O (io), B12 I/O (io), B13 M1~{-RDATA} (out), B14 HDC-I/O (io), C1 I/O (io), C2 A9-I/O (io), C3 TCLKIN-I/O (io), C4 GND (power), C5 I/O (io), C6 I/O (io), C7 GND (power), C8 VCC (power), C9 I/O (io), C10 I/O (io), C11 GND (power), C12 I/O (io), C13 M2-I/O (io), C14 I/O (io), D1 A11-I/O (io), D2 A8-I/O (io), D3 VCC (power), D12 VCC (power), D13 I/O (io), D14 ~{LDC}-I/O (io), E1 A7-I/O (io), E2 I/O (io), E3 I/O (io), E12 I/O (io), E13 NC, E14 I/O (io), F1 NC, F2 A12-I/O (io), F3 I/O (io), F12 I/O (io), F13 I/O (io), F14 I/O (io), G1 A6-I/O (io), G2 A13-I/O (io), G3 VCC (power), G12 VCC (power), G13 I/O (io), G14 ~{INIT}-I/O (io), H1 A14-I/O (io), H2 A5-IO (io), H3 GND (power), H12 GND (power), H13 I/O (io), H14 I/O (io), J1 NC, J2 A4-I/O (io), J3 I/O (io), J12 I/O (io), J13 I/O (io), J14 I/O (io), K1 A15-I/O (io), K2 I/O (io), K3 I/O (io), K12 I/O (io), K13 I/O (io), K14 I/O (io), L1 A3-I/O (io), L2 A2-I/O (io), L3 GND (power), L12 GND (power), L13 I/O (io), L14 NC, M1 I/O (io), M2 A0-~{WS}-I/O (io), M3 DOUT-I/O (io), M4 VCC (power), M5 D1-I/O (io), M6 D2-I/O (io), M7 GND (power), M8 VCC (power), M9 D5-I/O (io), M10 I/O (io), M11 VCC (power), M12 D7-I/O (io), M13 XTAL2(IN)-I/O (io), M14 I/O (io), N1 A1-CS2-I/O (io), N2 D0-DIN-I/O (io), N3 I/O (io), N4 RDY/~{BUSY}-~{BCLK}-I/O (io), N5 I/O (io), N6 NC, N7 D3-I/O (io), N8 D4-I/O (io), N9 ~{CS}0-I/O (io), N10 I/O (io), N11 D6-I/O (io), N12 I/O (io), N13 DONE~{-PG} (out), N14 I/O (io), P1 CCLK (io), P2 I/O (io), P3 I/O (io), P4 I/O (io), P5 NC, P6 ~{CS}1-I/O (io), P7 I/O (io), P8 NC, P9 NC, P10 I/O (io), P11 NC, P12 I/O (io), P13 BCLKIN-XTAL1-I/O (io), P14 ~{RESET} (in)

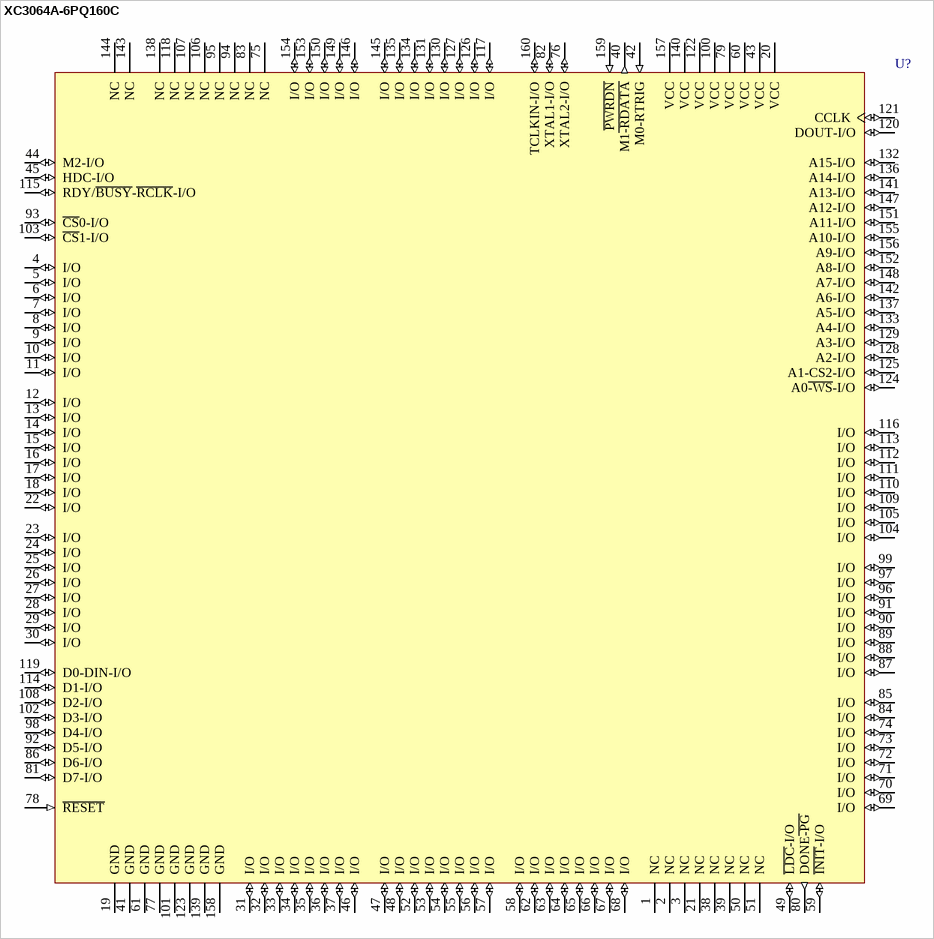
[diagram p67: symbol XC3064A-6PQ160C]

## XC3064A-6PQ160C
designator U?
Logic Cell Array with 224 CLBs, with 120 I/O Pins, 160-Pin PQFP, Commercial Grade; ComponentAvailability: Not for New Design
footprint PQ160_N (QFP, 160-Leads, Body 28 x 28mm, Pitch 0.65mm, IPC Medium Density)
footprint PQ160_L (QFP, 160-Leads, Body 28 x 28mm, Pitch 0.65mm, IPC High Density)
footprint PQ160_M (QFP, 160-Leads, Body 28 x 28mm, Pitch 0.65mm, IPC Low Density)
3D model XC3064A-PQ160 (160-Pin Plastic Quad Flat Pack (PQ160))
pins: 1 NC, 2 NC, 3 NC, 4 I/O (io), 5 I/O (io), 6 I/O (io), 7 I/O (io), 8 I/O (io), 9 I/O (io), 10 I/O (io), 11 I/O (io), 12 I/O (io), 13 I/O (io), 14 I/O (io), 15 I/O (io), 16 I/O (io), 17 I/O (io), 18 I/O (io), 19 GND (power), 20 VCC (power), 21 NC, 22 I/O (io), 23 I/O (io), 24 I/O (io), 25 I/O (io), 26 I/O (io), 27 I/O (io), 28 I/O (io), 29 I/O (io), 30 I/O (io), 31 I/O (io), 32 I/O (io), 33 I/O (io), 34 I/O (io), 35 I/O (io), 36 I/O (io), 37 I/O (io), 38 NC, 39 NC, 40 M1~{-RDATA} (out), 41 GND (power), 42 M0-RTRIG (in), 43 VCC (power), 44 M2-I/O (io), 45 HDC-I/O (io), 46 I/O (io), 47 I/O (io), 48 I/O (io), 49 ~{LDC}-I/O (io), 50 NC, 51 NC, 52 I/O (io), 53 I/O (io), 54 I/O (io), 55 I/O (io), 56 I/O (io), 57 I/O (io), 58 I/O (io), 59 ~{INIT}-I/O (io), 60 VCC (power), 61 GND (power), 62 I/O (io), 63 I/O (io), 64 I/O (io), 65 I/O (io), 66 I/O (io), 67 I/O (io), 68 I/O (io), 69 I/O (io), 70 I/O (io), 71 I/O (io), 72 I/O (io), 73 I/O (io), 74 I/O (io), 75 NC, 76 XTAL2-I/O (io), 77 GND (power), 78 ~{RESET} (in), 79 VCC (power), 80 DONE~{-PG} (out), 81 D7-I/O (io), 82 XTAL1-I/O (io), 83 NC, 84 I/O (io), 85 I/O (io), 86 D6-I/O (io), 87 I/O (io), 88 I/O (io), 89 I/O (io), 90 I/O (io), 91 I/O (io), 92 D5-I/O (io), 93 ~{CS}0-I/O (io), 94 NC, 95 NC, 96 I/O (io), 97 I/O (io), 98 D4-I/O (io), 99 I/O (io), 100 VCC (power), 101 GND (power), 102 D3-I/O (io), 103 ~{CS}1-I/O (io), 104 I/O (io), 105 I/O (io), 106 NC, 107 NC, 108 D2-I/O (io), 109 I/O (io), 110 I/O (io), 111 I/O (io), 112 I/O (io), 113 I/O (io), 114 D1-I/O (io), 115 RDY/~{BUSY}-~{RCLK}-I/O (io), 116 I/O (io), 117 I/O (io), 118 NC, 119 D0-DIN-I/O (io), 120 DOUT-I/O (io), 121 CCLK (io), 122 VCC (power), 123 GND (power), 124 A0~{-WS}-I/O (io), 125 A1-CS2-I/O (io), 126 I/O (io), 127 I/O (io), 128 A2-I/O (io), 129 A3-I/O (io), 130 I/O (io), 131 I/O (io), 132 A15-I/O (io), 133 A4-I/O (io), 134 I/O (io), 135 I/O (io), 136 A14-I/O (io), 137 A5-I/O (io), 138 NC, 139 GND (power), 140 VCC (power), 141 A13-I/O (io), 142 A6-I/O (io), 143 NC, 144 NC, 145 I/O (io), 146 I/O (io), 147 A12-I/O (io), 148 A7-I/O (io), 149 I/O (io), 150 I/O (io), 151 A11-I/O (io), 152 A8-I/O (io), 153 I/O (io), 154 I/O (io), 155 A10-I/O (io), 156 A9-I/O (io), 157 VCC (power), 158 GND (power), 159 ~{PWRDN} (in), 160 TCLKIN-I/O (io)

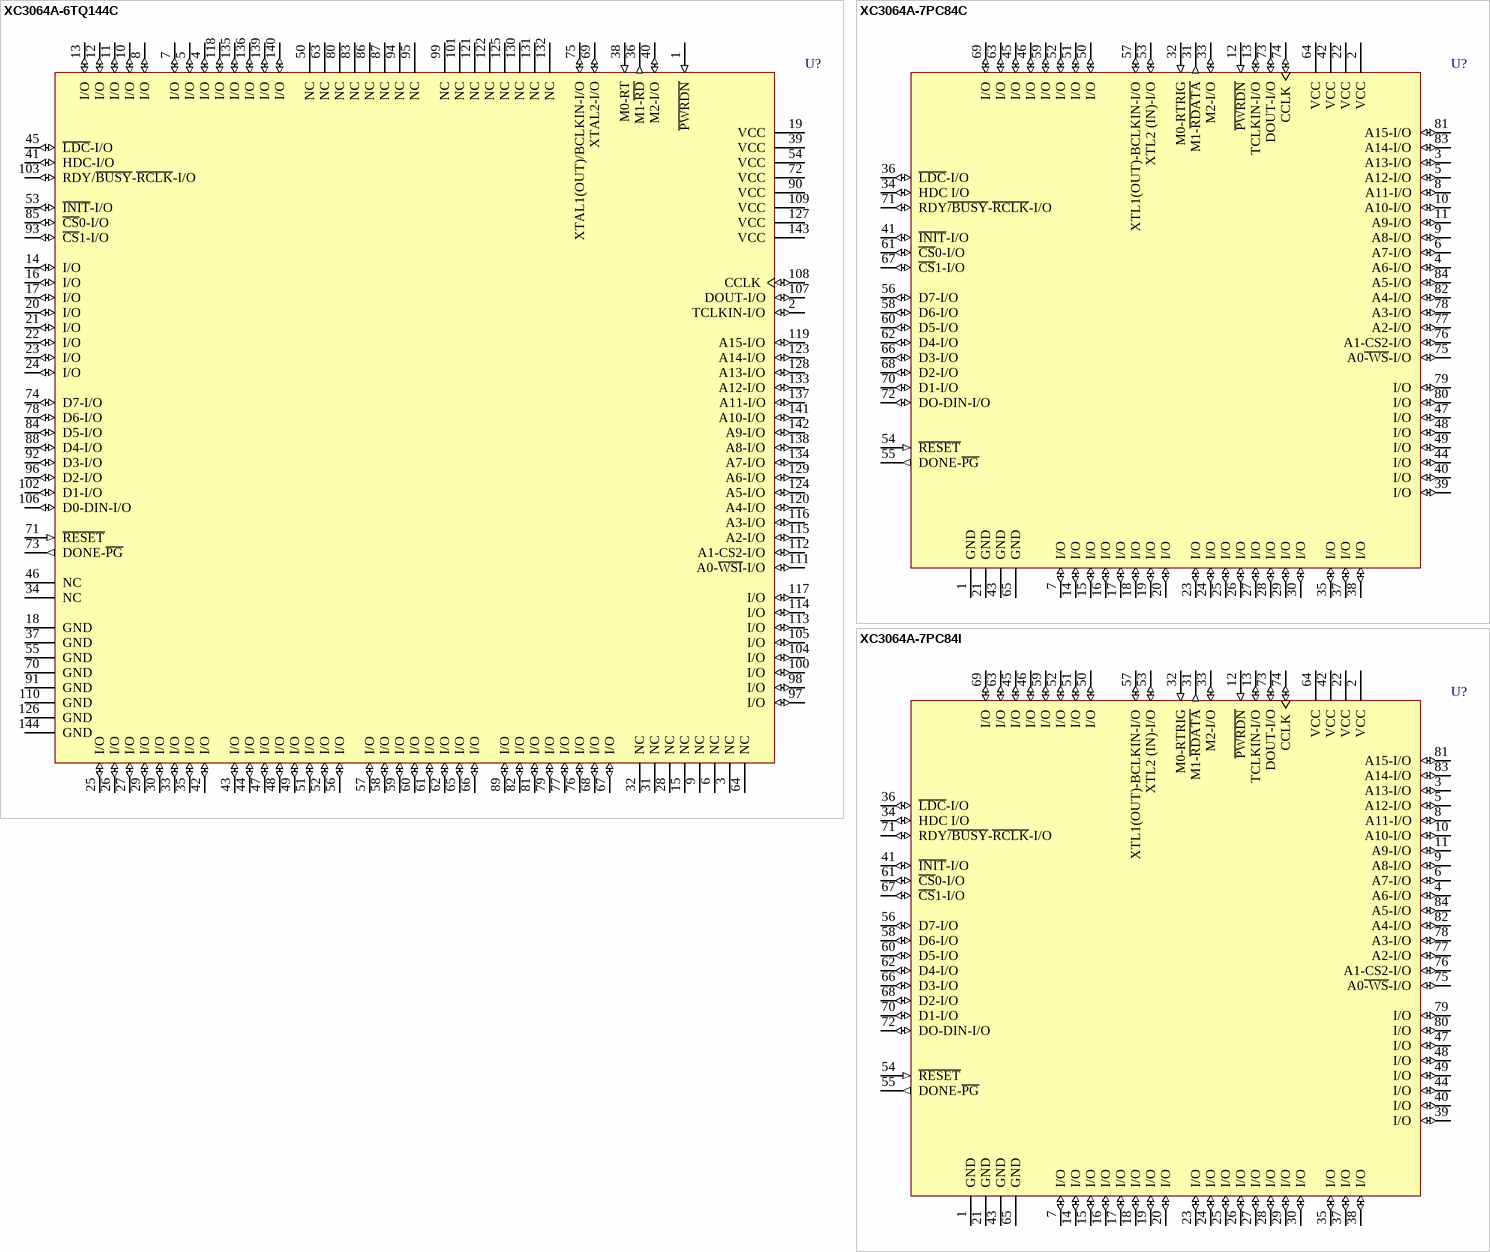
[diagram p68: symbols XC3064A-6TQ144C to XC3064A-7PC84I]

## XC3064A-6TQ144C
designator U?
Logic Cell Array with 224 CLBs, with 96 I/O Pins, 144-Pin TQFP, Commercial Grade; ComponentAvailability: Not for New Design
footprint TQ144_N (Thin QFP, 144-Leads, Body 20x20mm, Pitch 0.5mm, IPC Medium Density)
footprint TQ144_L (Thin QFP, 144-Leads, Body 20x20mm, Pitch 0.5mm, IPC High Density)
footprint TQ144_M (Thin QFP, 144-Leads, Body 20x20mm, Pitch 0.5mm, IPC Low Density)
3D model XC3064A-TQ144 (144-Pin Thin Quad Flat Pack (TQ144))
pins: 1 ~{PWRDN} (in), 2 TCLKIN-I/O (io), 3 NC, 4 I/O (io), 5 I/O (io), 6 NC, 7 I/O (io), 8 I/O (io), 9 NC, 10 I/O (io), 11 I/O (io), 12 I/O (io), 13 I/O (io), 14 I/O (io), 15 NC, 16 I/O (io), 17 I/O (io), 18 GND (power), 19 VCC (power), 20 I/O (io), 21 I/O (io), 22 I/O (io), 23 I/O (io), 24 I/O (io), 25 I/O (io), 26 I/O (io), 27 I/O (io), 28 NC, 29 I/O (io), 30 I/O (io), 31 NC, 32 NC, 33 I/O (io), 34 NC, 35 I/O (io), 36 M1-~{RD} (out), 37 GND (power), 38 M0-RT (in), 39 VCC (power), 40 M2-I/O (io), 41 HDC-I/O (io), 42 I/O (io), 43 I/O (io), 44 I/O (io), 45 ~{LDC}-I/O (io), 46 NC, 47 I/O (io), 48 I/O (io), 49 I/O (io), 50 NC, 51 I/O (io), 52 I/O (io), 53 ~{INIT}-I/O (io), 54 VCC (power), 55 GND (power), 56 I/O (io), 57 I/O (io), 58 I/O (io), 59 I/O (io), 60 I/O (io), 61 I/O (io), 62 I/O (io), 63 NC, 64 NC, 65 I/O (io), 66 I/O (io), 67 I/O (io), 68 I/O (io), 69 XTAL2-I/O (io), 70 GND (power), 71 ~{RESET} (in), 72 VCC (power), 73 DONE-~{PG} (out), 74 D7-I/O (io), 75 XTAL1(OUT)/BCLKIN-I/O (io), 76 I/O (io), 77 I/O (io), 78 D6-I/O (io), 79 I/O (io), 80 NC, 81 I/O (io), 82 I/O (io), 83 NC, 84 D5-I/O (io), 85 ~{CS}0-I/O (io), 86 NC, 87 NC, 88 D4-I/O (io), 89 I/O (io), 90 VCC (power), 91 GND (power), 92 D3-I/O (io), 93 ~{CS}1-I/O (io), 94 NC, 95 NC, 96 D2-I/O (io), 97 I/O (io), 98 I/O (io), 99 NC, 100 I/O (io), 101 NC, 102 D1-I/O (io), 103 RDY/~{BUSY}-~{RCLK}-I/O (io), 104 I/O (io), 105 I/O (io), 106 D0-DIN-I/O (io), 107 DOUT-I/O (io), 108 CCLK (io), 109 VCC (power), 110 GND (power), 111 A0-~{WSI}-I/O (io), 112 A1-CS2-I/O (io), 113 I/O (io), 114 I/O (io), 115 A2-I/O (io), 116 A3-I/O (io), 117 I/O (io), 118 I/O (io), 119 A15-I/O (io), 120 A4-I/O (io), 121 NC, 122 NC, 123 A14-I/O (io), 124 A5-I/O (io), 125 NC, 126 GND (power), 127 VCC (power), 128 A13-I/O (io), 129 A6-I/O (io), 130 NC, 131 NC, 132 NC, 133 A12-I/O (io), 134 A7-I/O (io), 135 I/O (io), 136 I/O (io), 137 A11-I/O (io), 138 A8-I/O (io), 139 I/O (io), 140 I/O (io), 141 A10-I/O (io), 142 A9-I/O (io), 143 VCC (power), 144 GND (power)

## XC3064A-7PC84C
designator U?
Logic Cell Array with 224 CLBs, with 70 I/O Pins, 84-Pin PLCC, Commercial Grade; ComponentAvailability: Not for New Design
footprint PC84_N (Leaded Chip Carrier, 84-Leads, Body 29.3x29.3mm, Pitch 1.27mm, IPC Medium Density)
footprint PC84_L (Leaded Chip Carrier, 84-Leads, Body 29.3x29.3mm, Pitch 1.27mm, IPC High Density)
footprint PC84_M (Leaded Chip Carrier, 84-Leads, Body 29.3x29.3mm, Pitch 1.27mm, IPC Low Density)
3D model XC3064A-PC84 (84-Pin Plastic Leaded Chip Carrier (PC84))
pins: 1 GND (power), 2 VCC (power), 3 A13-I/O (io), 4 A6-I/O (io), 5 A12-I/O (io), 6 A7-I/O (io), 7 I/O (io), 8 A11-I/O (io), 9 A8-I/O (io), 10 A10-I/O (io), 11 A9-I/O (io), 12 ~{PWRDN} (in), 13 TCLKIN-I/O (io), 14 I/O (io), 15 I/O (io), 16 I/O (io), 17 I/O (io), 18 I/O (io), 19 I/O (io), 20 I/O (io), 21 GND (power), 22 VCC (power), 23 I/O (io), 24 I/O (io), 25 I/O (io), 26 I/O (io), 27 I/O (io), 28 I/O (io), 29 I/O (io), 30 I/O (io), 31 M1-~{RDATA} (out), 32 M0-RTRIG (in), 33 M2-I/O (io), 34 HDC I/O (io), 35 I/O (io), 36 ~{LDC}-I/O (io), 37 I/O (io), 38 I/O (io), 39 I/O (io), 40 I/O (io), 41 ~{INIT}-I/O (io), 42 VCC (power), 43 GND (power), 44 I/O (io), 45 I/O (io), 46 I/O (io), 47 I/O (io), 48 I/O (io), 49 I/O (io), 50 I/O (io), 51 I/O (io), 52 I/O (io), 53 XTL2 (IN)-I/O (io), 54 ~{RESET} (in), 55 DONE-~{PG} (out), 56 D7-I/O (io), 57 XTL1(OUT)-BCLKIN-I/O (io), 58 D6-I/O (io), 59 I/O (io), 60 D5-I/O (io), 61 ~{CS}0-I/O (io), 62 D4-I/O (io), 63 I/O (io), 64 VCC (power), 65 GND (power), 66 D3-I/O (io), 67 ~{CS}1-I/O (io), 68 D2-I/O (io), 69 I/O (io), 70 D1-I/O (io), 71 RDY~{/BUSY}-~{RCLK}-I/O (io), 72 DO-DIN-I/O (io), 73 DOUT-I/O (io), 74 CCLK (io), 75 A0~{-WS}-I/O (io), 76 A1-CS2-I/O (io), 77 A2-I/O (io), 78 A3-I/O (io), 79 I/O (io), 80 I/O (io), 81 A15-I/O (io), 82 A4-I/O (io), 83 A14-I/O (io), 84 A5-I/O (io)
